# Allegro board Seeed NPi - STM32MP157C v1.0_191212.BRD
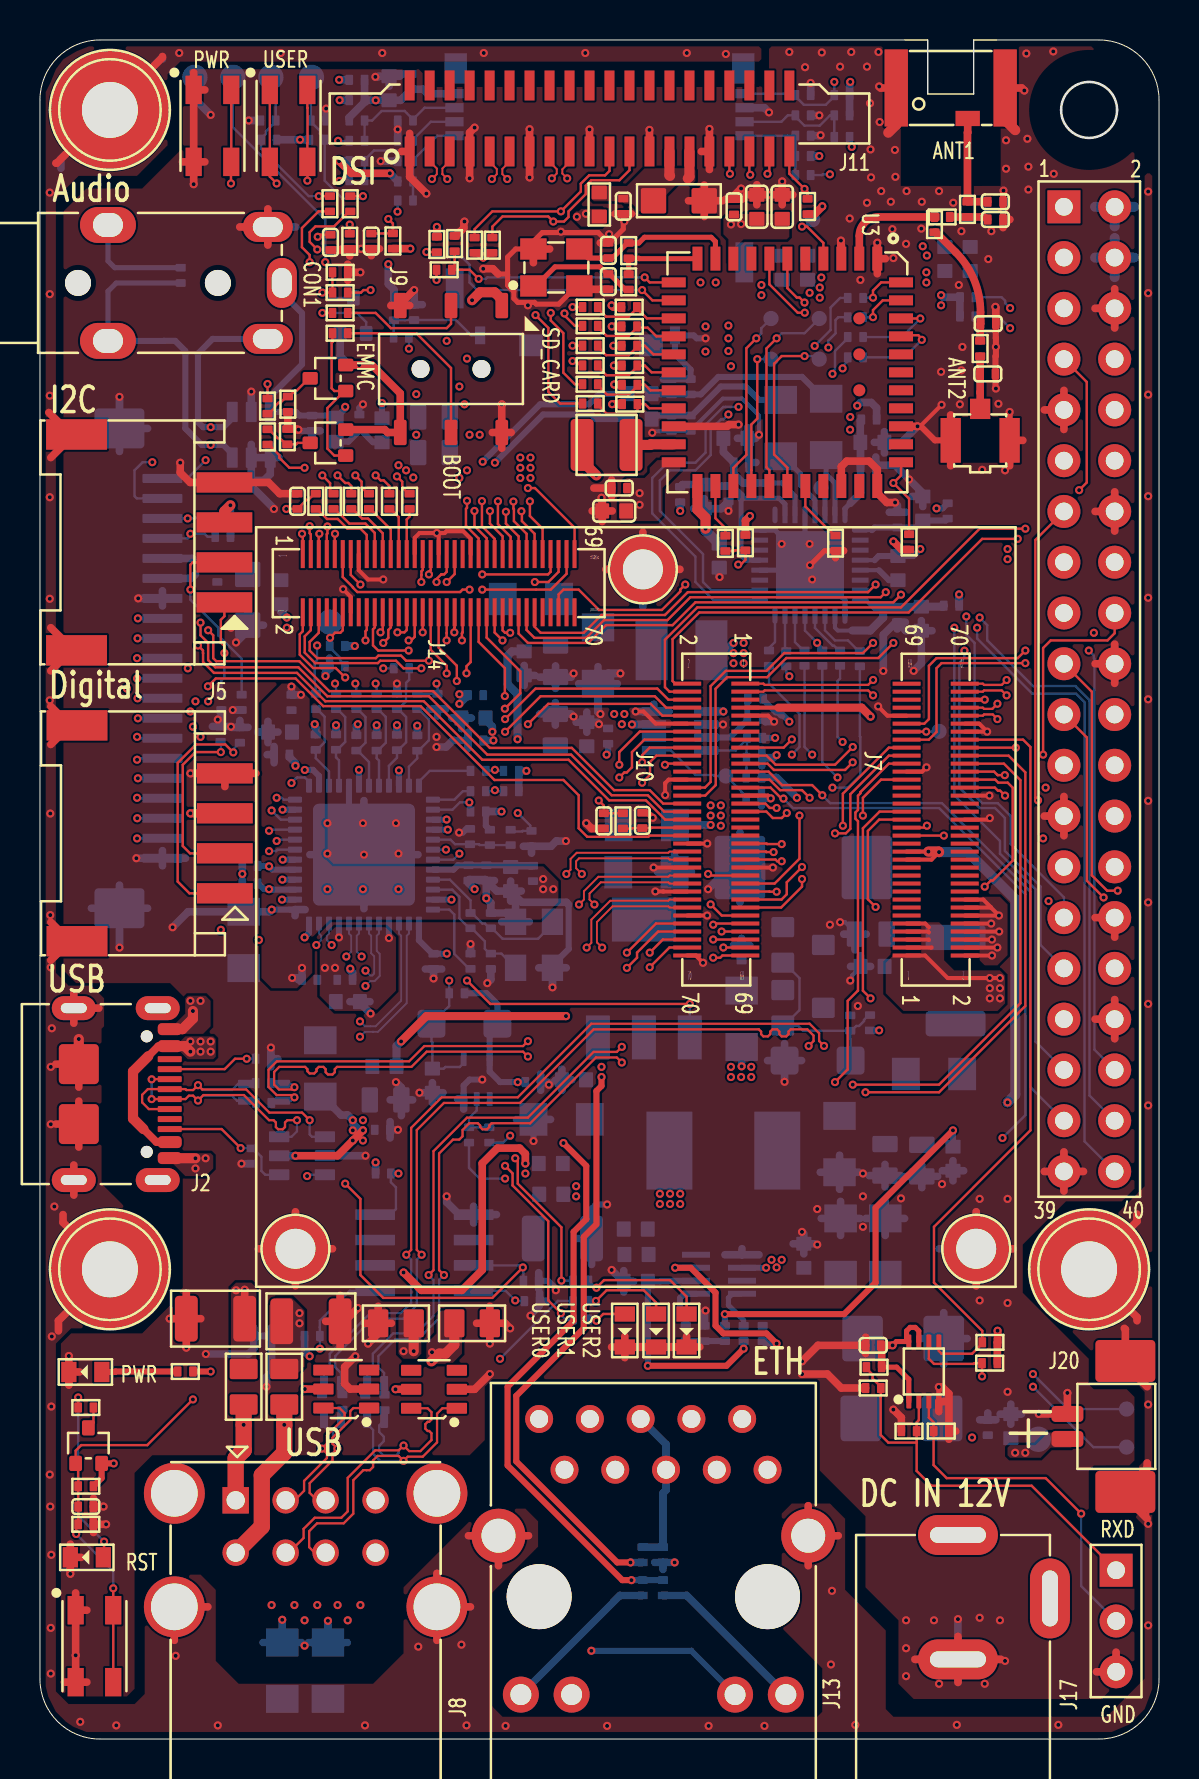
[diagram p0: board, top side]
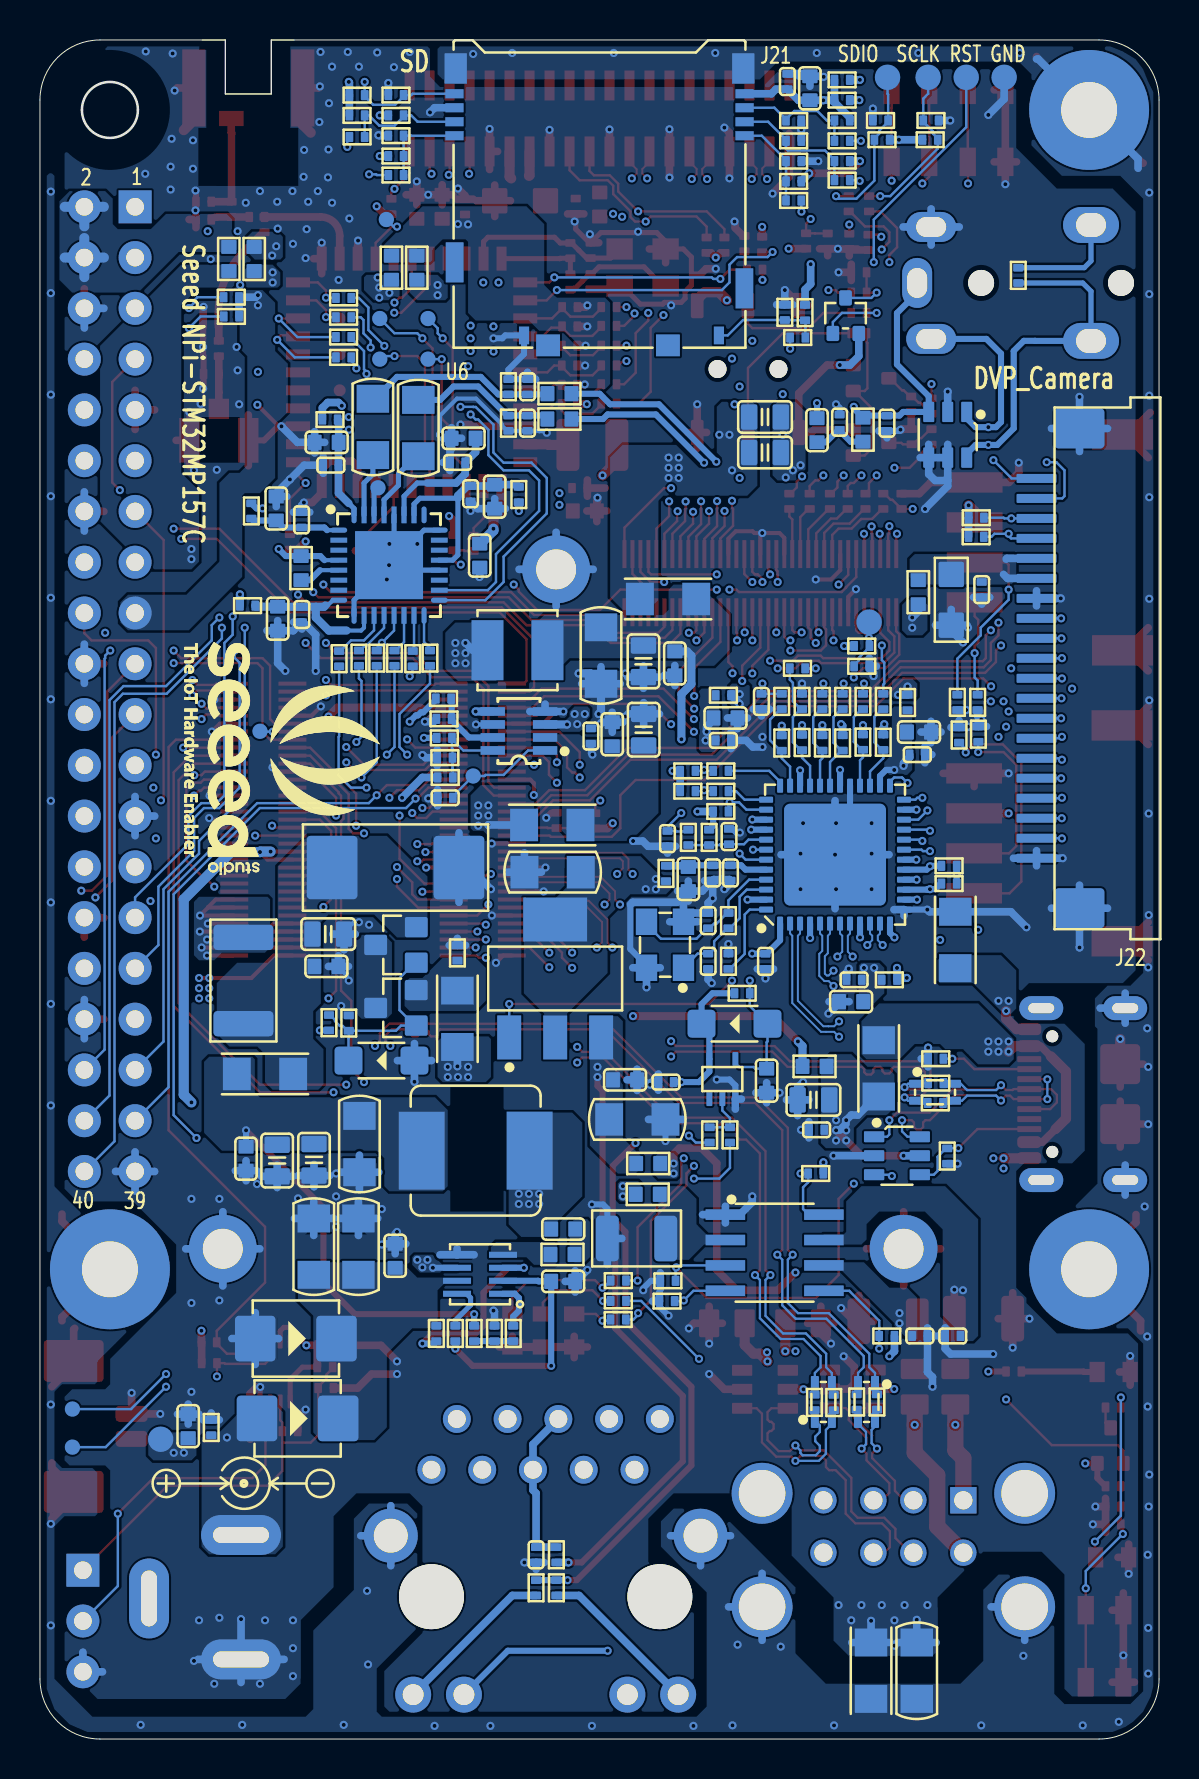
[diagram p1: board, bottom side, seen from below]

Outline 56 x 85 mm; copper layers: TOP, LYR2_GND, LYR3, LYR4, LYR5_PWR, BOTTOM. Coordinates in mm from the lower left corner of the outline.
Outline path: 0,82 0,3 arc(0.88,0.88) 3,0 53,0 arc(55.12,0.88) 56,3 56,82 arc(55.12,84.12) 53,85 46.73,85 46.73,82.3 44.42,82.3 44.42,85 3,85 arc(0.88,84.12) 0,82 ; 51.1,81.5 arc(52.5,82.9) 53.9,81.5 arc(52.5,80.1) 51.1,81.5

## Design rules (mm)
constraint set DEFAULT: min track width 0.121
net group DIFFPAIR2: nets GBE1_TRN0 GBE1_TRP0
net group DIFFPAIR3: nets GBE1_TRN1 GBE1_TRP1
net group DIFFPAIR4: nets GBE1_TRN2 GBE1_TRP2
net group DIFFPAIR5: nets GBE1_TRN3 GBE1_TRP3
net group DIFFPAIR36: nets HOST_USB1_DM HOST_USB1_DP
net group DSI_CK: nets DSI_CK_N DSI_CK_P
net group DSI_D0: nets DSI_D0_N DSI_D0_P
net group DSI_D1: nets DSI_D1_N DSI_D1_P
net group HOST_USB2: nets HOST_USB2_DM HOST_USB2_DP
net group OTG_FS: nets OTG_FS_DM OTG_FS_DP
net group OTG_USB: nets OTG_USB_DM OTG_USB_DP
net group USB1: nets USB1_N USB1_P
net group USB2: nets USB2_N USB2_P
net group DVP: nets DVP_D0 DVP_D1 DVP_D2 DVP_D3 DVP_D4 DVP_D5 DVP_D6 DVP_D7 DVP_HSYNC DVP_PCLK DVP_VSYNC MOC1
net group ETH_RX: nets ETH_RX_CLK ETH_RX_DV ETH_RXD0 ETH_RXD1 ETH_RXD2 ETH_RXD3
net group ETH_TX: nets ETH_GTX_CLK ETH_TX_EN ETH_TXD0 ETH_TXD1 ETH_TXD2 ETH_TXD3
net group MG1_RGMII1_TX: nets RGMII1_TD0
net group RGMII_RX: nets RGMII1_RCLK RGMII1_RCTL RGMII1_RD0 RGMII1_RD1 RGMII1_RD2 RGMII1_RD3
net group RGMII_TX: nets RGMII1_TCLK RGMII1_TCTL RGMII1_TD1 RGMII1_TD2 RGMII1_TD3
net group SD: nets SD_CLK SD_CMD SD_DAT0 SD_DAT1 SD_DAT2 SD_DAT3
net group SDMMC1: nets SDMMC1_CK SDMMC1_CMD SDMMC1_D0 SDMMC1_D1 SDMMC1_D2 SDMMC1_D3
net group SDMMC3: nets SDMMC3_CLK SDMMC3_CMD SDMMC3_D0 SDMMC3_D1 SDMMC3_D2 SDMMC3_D3
nets with their own width: min track width 0.381; nets GND

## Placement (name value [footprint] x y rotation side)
ANT1  ACA-5036-A2-CC-S  [ACA5036]  45.57 82.6 270 top
C1  10pF  [C0402]  2.29 11.63 0 top
C2  47uF  [AVX_B]  8.78 21.03 180 top
C3  100nF  [C0402]  10.32 20.16 0 bottom
C4  100pF  [C0402]  31.6 67.65 90 bottom
C5  100pF  [C0402]  31.6 65.83 270 bottom
C6  100nF  [C0402]  11.97 20.16 180 bottom
C7  47uF  [AVX_B]  13.56 20.9 0 top
C8  22pF  [C0402]  28.44 74.47 90 top
C9  22pF  [C0402]  28.44 72.91 270 top
C10  1uF  [C0603]  28.74 61.44 180 top
C11  22pF  [C0402]  30.14 45.96 90 top
C12  100nF  [C0402]  28.99 62.58 180 top
C13  100nF  [C0402]  29.19 76.68 270 top
C14  22pF  [C0402]  28.22 45.93 270 top
C15  10uF  [AVX_A]  31.97 76.96 0 top
C16  100nF  [C0402]  34.73 76.65 90 top
C17  10uF  [C0603]  35.87 76.65 90 top
C18  10uF  [C0603]  37.14 76.65 90 top
C19  1nF  [C0402]  35.72 47.09 0 bottom
C20  10pF  [C0402]  12.89 61.92 90 top
C21  10pF  [C0402]  47.43 68.29 0 top
C22  10pF  [C0402]  47.45 70.81 0 top
C23  10pF  [C0402]  47.81 76.91 0 top
C24  10pF  [C0402]  47.81 76.02 0 top
C25  100nF  [C0603]  48.58 15.65 90 bottom
C26  10uF  [C0805]  25.79 50.49 90 bottom
C27  10uF  [C0603]  27.36 50.27 90 bottom
C28  10pF  [C0402]  19.9 51.91 270 bottom
C29  100nF  [C0402]  28.43 50.18 90 bottom
C30  10uF  [C0603]  21.69 51.08 180 bottom
C31  100uF  [C1206]  30.35 43.37 0 bottom
C32  10uF  [C0603]  12.01 50.38 180 bottom
C33  100nF  [C0402]  12.1 49.25 180 bottom
C34  100nF  [C0402]  21.8 49.96 180 bottom
C35  100nF  [C0402]  41.7 19.7 0 top
C36  100nF  [C0603]  29.81 25.51 180 bottom
C37  4.7uF  [C1206]  42.3 24.63 90 bottom
C38  4.7uF  [C1206]  40.06 24.63 90 bottom
C39  100nF  [C0603]  38.22 24.17 90 bottom
C40  22uF  [C1206]  40.01 29.77 270 bottom
C41  100nF  [C0402]  21.45 43.33 270 bottom
C42  10nF  [C0402]  22.33 43.33 270 bottom
C43  10uF  [C0603]  23.55 43.02 270 bottom
C44  22uF  [C1206]  27.93 54.2 270 bottom
C45  22uF  [C0805]  42.29 28.98 270 bottom
C46  100nF  [C0603]  24.23 53.81 270 bottom
C47  22pF  [C0402]  22.56 40.94 270 bottom
C48  100nF  [C0402]  31.17 9.22 270 bottom
C49  10uF  [C0603]  33.99 59.2 270 bottom
C50  22uF  [C0805]  44.13 28.94 270 bottom
C51  22pF  [C0402]  22.56 38.91 90 bottom
C52  100nF  [C0402]  19.7 38.9 270 bottom
C53  100nF  [C0603]  45.69 29.03 270 bottom
C54  100nF  [C0603]  29.82 22.9 180 bottom
C55  100nF  [C0402]  15.26 37.98 0 bottom
C56  330uF  [AVX_D]  38.21 43.6 180 bottom
C57  10uF  [C0603]  26.72 32.98 180 bottom
C58  10uF  [C0603]  15.41 36.89 0 bottom
C59  100uF  [C1206]  26.11 31 180 bottom
C60  10uF  [C0805]  41.57 40.27 180 bottom
C61  100nF  [C0603]  41.67 38.65 180 bottom
C62  100nF  [C0402]  24.67 32.86 0 bottom
C63  22uF  [C0805]  25.8 53.92 270 bottom
C64  10uF  [C0805]  19.72 66.14 180 bottom
C65  10uF  [C0603]  19.64 32.94 270 bottom
C66  10uF  [C0805]  19.72 64.36 180 bottom
C68  33pF  [C0402]  13.61 65.83 270 bottom
C70  10uF  [C0603]  44.18 61.56 90 bottom
C71  33pF  [C0402]  15.98 65.88 90 bottom
C72  10uF  [C0603]  44.11 56.05 270 bottom
C73  4.7pF  [C0402]  24.6 45.05 270 bottom
C74  10uF  [C0603]  17.12 65.48 90 bottom
C75  100nF  [C0402]  42.91 60.99 90 bottom
C76  100nF  [C0402]  42.9 56.26 270 bottom
C77  47uF  [AVX_B]  26.14 25.04 0 bottom
C78  10uF  [C0603]  41.65 64.87 0 bottom
C79  100nF  [C0402]  41.44 63.73 0 bottom
C80  10pF  [C0402]  21.52 45.15 90 bottom
C81  100uF  [C1206]  39.34 65.64 90 bottom
C82  100nF  [C0402]  18.6 82.92 90 bottom
C83  10uF  [C0603]  17.47 82.58 90 bottom
C84  100uF  [C1206]  37.07 65.58 90 bottom
C90  100nF  [C0402]  35.1 63.86 0 bottom
C91  1nF  [C1206]  12.12 3.42 90 bottom
C92  10uF  [C0603]  34.8 65.07 0 bottom
C93  100nF  [C0402]  34.45 62.3 270 bottom
C94  10pF  [C0402]  16.58 74.94 270 top
C95  10uF  [C0603]  33.24 62.15 270 bottom
C97  10uF  [AVX_A]  10.4 56.99 270 bottom
C98  10uF  [C0805]  17.29 31.98 0 bottom
C99  100nF  [C0402]  17.14 30.48 0 bottom
C100  100nF  [C0402]  8.87 57.5 270 bottom
C102  10pF  [C0402]  14.54 74.88 270 top
CON1  PJ322  [AUDIO_5P_MJ2135_5D6_14_7X7X6MM]  -2.6 72.85 0 top
D1  ESDPSA0402V05  [D0402]  2.29 10.74 0 top
D2  ESDPSA0402V05  [D0402]  10 50.23 90 bottom
D3  ESDPSA0402V05  [D0402]  9.04 50.27 90 bottom
D4  MBRS240LT3  [DO_214AA_SMB]  43.11 16.04 180 bottom
D5  ESDPSA0402V05  [D0402]  38.18 82.24 0 bottom
D6  ESDPSA0402V05  [D0402]  38.18 81.23 0 bottom
D7  ESDPSA0402V05  [D0402]  38.18 80.21 0 bottom
D8  ESDPSA0402V05  [D0402]  45.1 15.4 0 top
D9  ESDPSA0402V05  [D0402]  43.49 15.4 180 top
D10  1N4148W  [SOD_123]  21.24 35.79 0 bottom
D11  SMBJ24CA  [DO_214AA_SMB]  43.19 20.03 180 bottom
D12  ESDPSA0402V05  [D0402]  18.73 71.37 90 bottom
D13  ESDPSA0402V05  [D0402]  18.28 80.97 180 bottom
D14  ESDPSA0402V05  [D0402]  18.28 79.95 180 bottom
D15  ESDPSA0402V05  [D0402]  18.28 78.94 180 bottom
D16  1N4148W  [SOD_123]  38.91 33.94 0 bottom
D17  ESDPSA0402V05  [D0402]  9.08 51.86 270 bottom
D18  ESDPSA0402V05  [D0402]  10.09 51.86 270 bottom
D20  ESDPSA0402V05  [D0402]  13.94 80.97 0 bottom
D21  ESDPSA0402V05  [D0402]  11.41 80.97 180 bottom
F1  3A  [F1812]  45.82 37.95 90 bottom
FB1  100R  [L0603]  30 67.31 180 bottom
FB2  100R  [L0603]  30.01 66.04 180 bottom
FB3  30R  [L0603]  27.99 76.77 90 top
FB4  120R  [L0603]  46.55 74.04 90 bottom
FB5  120R  [L0603]  45.28 74.04 90 bottom
FB6  120R  [L0402]  12.58 51.85 270 bottom
FB7  120R  [L0603]  38.41 73.61 90 bottom
FB8  120R  [L0603]  37.14 73.61 90 bottom
FB9  120R  [L0402]  24.67 43.3 90 bottom
FB10  120R  [L0603]  25.56 28.79 0 bottom
FB11  2500R  [L0603]  14.82 65.5 270 bottom
FB12  120R  [L0402]  15.86 83.01 0 bottom
FB13  120R  [L0402]  15.86 81.99 0 bottom
FB14  30R  [L0603]  12.05 57.38 90 bottom
J1  4P-2.0mm-90D  [JST4P_SMD_2_0_90D]  9.23 59.86 90 top
J2  USB2.0 Type C  [USB2_0_TYPE_C]  6.44 32.26 0 top
J3  Header 1P  [PTH_2_75MM_5D9]  3.5 81.5 0 top
J4  Header 1P  [PTH_2_75MM_5D9]  3.5 23.5 0 top
J5  4P-2.0mm-90D  [JST4P_SMD_2_0_90D]  9.25 45.31 90 top
J6  Header 1P  [PTH_2MM_3D4]  46.85 24.53 180 top
J7  DF40C(2.0)-70DS-0.4V(51)  [BTB2X35_0D4_16_6X3X2MM]  44.82 46 180 top
J8  USB-AF-90  [ST-USB-201C]  13.29 6.61 180 top
J9  Toggle Switch_2CH  [SW6_2D54_SMD_7_0X3_5X1_5MM]  20.57 68.54 270 top
J10  DF40C(2.0)-70DS-0.4V(51)  [BTB2X35_0D4_16_6X3X2MM]  33.84 46 0 top
J11  YL002-007-020  [HEADER_2X20_1MM]  28 81.07 180 top
J12  Header 1P  [PTH_2MM_3D4]  30.17 58.52 180 top
J13  48F-01GY2DPL2NL  [RJ45_18P_48F-01GY2DPLXNL]  30.69 7.12 0 top
J14  DF40C(2.0)-70DS-0.4V(51)  [BTB2X35_0D4_16_6X3X2MM]  19.95 57.82 90 top
J15  Header 1P  [PTH_2MM_3D4]  12.78 24.53 180 top
J16  U.FL-R-SMT-1(10)  [U-FL3P-SMD-2_6X2_6X1_0MM]  47.05 64.97 90 top
J17  DC-005  [DC_JACK_DC_005_14_2X11X9MM]  45.59 7.03 90 top
J18  Header 1P  [PTH_2_75MM_5D9]  52.5 23.5 0 top
J19  Header 2x20 2.54mm  [HEADER2X20P_2D54_DIP]  52.51 52.52 0 top
J20  Header 1x2 1.25mm  [JST2P_1D25_7_55X3_9X4_8MM]  51.41 15.64 90 top
J21  SCHA5B0200  [SD-MICRO-SCHA5B0300]  28 80.21 0 bottom
J22  YL002-009-020  [JST20P_1D0_27_1X5_3X2_5MM]  6.13 53.57 90 bottom
J24  Header 1x3 2.54mm  [HEADER3P_2D54_DIP]  53.85 5.9 0 top
L1  3.3uH  [L3X3MM]  28.35 64.74 180 top
L2  1uH  [L4X4MM]  32.1 54.47 180 bottom
L3  10uH  [L6_5X6_5]  34.2 29.44 0 bottom
L4  90R  [L2012]  14.64 16.86 270 bottom
L5  90R  [L2012]  16.8 16.86 90 bottom
L6  90R  [L2012]  11.21 32.36 180 bottom
LED1  Blue  [LED0603]  2.34 9.09 180 top
LED2  Red  [LED0603]  30.83 20.44 270 top
LED3  Red  [LED0603]  32.36 20.44 270 top
LED4  Green  [LED0603]  2.27 18.36 180 top
LED5  Red  [LED0603]  29.27 20.44 270 top
NOREF  -  []  9.94 66.01 270 bottom
Q1  CJ2101  [SOT323]  2.42 14.68 0 top
Q2  CJ2101  [SOT323]  14.41 68.07 90 top
Q3  CJ2101  [SOT323]  14.41 64.84 90 top
Q6  FDT434P  [SOT223_4]  30.22 38.05 90 bottom
Q7  IRLML6402TRPBF  [SOT23]  38.19 36.58 90 bottom
Q8  IRLML6402TRPBF  [SOT23]  38.19 39.73 90 bottom
Q9  CJ2101  [SOT323]  15.69 71.21 180 bottom
R1  2K  [R0402]  2.29 16.58 180 top
R2  10K  [R0402]  2.29 12.65 180 top
R3  1K  [R0402]  11.39 65.14 270 top
R4  10K  [R0402]  32.56 67.65 90 bottom
R5  10K  [R0402]  12.38 65.15 90 top
R6  10K  [R0402]  32.56 65.83 270 bottom
R7  10K  [R0402]  12.4 66.78 270 top
R8  1K  [R0402]  11.39 66.68 90 top
R9  4.7K  [R0402]  13.62 20.16 180 bottom
R10  4.7K  [R0402]  17.18 28.29 180 bottom
R11  10K  [R0402]  15.02 73.38 180 top
R12  1K  [R0402]  15.02 72.36 0 top
R13  2K  [R0402]  27.06 21.92 0 bottom
R14  2K  [R0402]  27.06 22.93 0 bottom
R15  1K  [R0402]  15.02 71.35 0 top
R16  1K  [R0402]  15.02 70.33 180 top
R17  4.7K  [R0402]  24.62 21.91 180 bottom
R18  4.7K  [R0402]  21.75 74.73 90 top
R19  10K  [R0402]  19.86 74.77 270 top
R20  4.7K  [R0402]  24.58 22.92 180 bottom
R21  4.7K  [R0402]  22.64 74.73 90 top
R22  10K  [R0402]  20.75 74.81 270 top
R23  33R  [R0402]  27.53 71.64 0 top
R24  33R  [R0402]  27.53 70.7 0 top
R25  33R  [R0402]  27.53 69.71 0 top
R26  33R  [R0402]  27.53 68.72 0 top
R27  33R  [R0402]  27.53 67.78 0 top
R28  33R  [R0402]  27.53 66.81 0 top
R29  1M  [R0402]  29.46 74.46 90 top
R30  0R  [R0402]  29.46 72.9 270 top
R31  10K  [R0402]  29.49 71.63 180 top
R32  10K  [R0402]  29.49 70.67 180 top
R33  10K  [R0402]  29.5 69.7 180 top
R34  10K  [R0402]  29.5 68.71 180 top
R35  10K  [R0402]  29.51 67.75 180 top
R36  10K  [R0402]  29.52 66.78 180 top
R37  49.9R  [R0402]  29.17 45.93 90 top
R38  22R  [R0402]  34.3 59.82 270 top
R39  10K  [R0402]  35.3 59.85 270 top
R40  10K  [R0402]  38.41 76.67 270 top
R41  49.9R  [R0402]  18.5 61.92 90 top
R42  0R  [R0402]  39.81 59.83 270 top
R43  49.9R  [R0402]  17.48 61.92 90 top
R44  49.9R  [R0402]  16.47 61.92 90 top
R45  49.9R  [R0402]  15.58 61.92 90 top
R46  49.9R  [R0402]  14.69 61.92 90 top
R47  10K  [R0402]  43.49 59.89 270 top
R48  100R  [R0402]  13.8 61.92 90 top
R49  0R  [R0402]  45.14 76.15 180 top
R50  0R  [R0402]  46.41 76.53 270 top
R51  0R  [R0402]  44.76 75.76 90 top
R52  0R  [R0402]  47.05 69.56 90 top
R53  49.9R  [R0402]  18.09 53.57 0 bottom
R54  4.7K  [R0402]  46.43 72.13 0 bottom
R55  4.7K  [R0402]  46.42 71.17 0 bottom
R56  49.9R  [R0402]  13.8 51.91 270 bottom
R57  49.9R  [R0402]  14.82 51.91 270 bottom
R58  49.9R  [R0402]  15.83 51.91 270 bottom
R59  49.9R  [R0402]  16.85 51.91 270 bottom
R60  1K  [R0402]  17.86 51.91 90 bottom
R61  100R  [R0402]  18.88 51.91 270 bottom
R62  0R  [R0402]  21.8 52.22 0 bottom
R63  0R  [R1206]  30.36 45.73 180 bottom
R64  10K  [R0402]  14.82 49.87 90 bottom
R65  10K  [R0402]  13.8 49.87 90 bottom
R66  1K  [R0402]  17.86 49.85 90 bottom
R67  100K  [R0402]  35.77 50.09 0 bottom
R68  10K  [R0402]  15.83 49.83 90 bottom
R69  10K  [R0402]  16.85 49.83 90 bottom
R70  10K  [R0402]  18.88 49.83 90 bottom
R71  40.2K  [R0402]  35.78 51.04 0 bottom
R72  0R  [R0402]  14.12 16.86 270 bottom
R73  0R  [R0402]  21.93 48.43 180 bottom
R74  10K  [R0402]  23.58 48.43 180 bottom
R75  180K  [R0402]  35.81 52.05 180 bottom
R76  33R  [R0402]  40.81 72.09 0 bottom
R77  33R  [R0402]  40.81 71.13 0 bottom
R78  33R  [R0402]  40.81 70.14 0 bottom
R79  33R  [R0402]  40.81 69.12 0 bottom
R80  0R  [R0402]  15.13 16.86 270 bottom
R81  10K  [R0402]  40.13 82.24 180 bottom
R82  10K  [R0402]  40.13 81.23 180 bottom
R83  33R  [R0402]  40.13 80.15 180 bottom
R84  0R  [R0402]  21.93 47.42 180 bottom
R85  1.5K  [R0402]  23.58 47.42 180 bottom
R86  0R  [R0402]  17.24 16.84 90 bottom
R87  0R  [R0402]  16.28 16.83 90 bottom
R88  0R  [R0805]  10.19 17.62 270 top
R89  4.7K  [R0402]  21.93 46.4 180 bottom
R90  0R  [R0805]  12.23 17.62 90 top
R91  10K  [R0402]  41.74 18.6 0 top
R92  10K  [R0402]  38.18 79.19 180 bottom
R93  33R  [R0402]  38.18 78.24 180 bottom
R94  10K  [R0402]  22.51 45.11 90 bottom
R95  49.9R  [R0402]  23.55 45.11 270 bottom
R96  100K  [R0402]  41.7 17.56 180 top
R97  4.7K  [R0402]  47.53 18.8 180 top
R98  4.7K  [R0402]  47.54 19.85 180 top
R99  0R  [R1206]  24.57 57.03 0 bottom
R100  1M  [R0402]  21.55 40.94 270 bottom
R101  33R  [R0402]  15.53 76.81 270 top
R102  1K  [R0402]  31.17 7.57 270 bottom
R103  0R  [R0402]  30.16 9.22 90 bottom
R104  1K  [R0402]  30.16 7.57 270 bottom
R105  12.1K  [R0402]  21.55 38.91 90 bottom
R106  10K  [R0402]  10.51 43.68 180 bottom
R107  10K  [R0402]  10.51 42.8 180 bottom
R108  10K  [R0402]  20.86 37.31 180 bottom
R109  0R  [R0402]  13.5 37.98 0 bottom
R110  0R  [R0805]  17.81 20.8 180 top
R111  33R  [R0402]  14.51 76.81 270 top
R112  4.7K  [R0402]  13.86 80.01 0 bottom
R113  4.7K  [R0402]  11.45 80.01 180 bottom
R114  0R  [R0805]  21.62 20.8 0 top
R115  20R  [R0603]  29.85 24.24 180 bottom
R116  2.2k  [R0402]  45.42 61.44 90 bottom
R117  0R  [R0402]  45.61 56.7 180 bottom
R118  0R  [R0402]  11.17 32.81 180 bottom
R119  0R  [R0603]  25.59 27.25 180 bottom
R120  0R  [R0402]  11.19 31.82 180 bottom
R121  5.1K  [R0402]  10.6 29.17 270 bottom
R122  5.1K  [R0402]  11.17 34.03 0 bottom
R123  4.7K  [R0402]  14.88 54.68 180 bottom
R124  4.7K  [R0402]  14.88 53.67 180 bottom
R125  0R  [R0603]  17.24 33.65 180 bottom
R126  0R  [R0603]  42.93 58.58 270 bottom
R127  1M  [R0402]  36.16 20.29 270 bottom
R128  0R  [R0402]  21.47 30.22 90 bottom
R129  0R  [R0402]  22.49 30.22 90 bottom
R130  0R  [R1206]  14.03 33.55 270 bottom
R131  0R  [R0402]  41.49 66.01 180 bottom
R132  0R  [R1206]  10.19 39.98 270 bottom
R133  0R  [R0402]  20.23 73.5 0 top
R134  2K  [R0402]  27.07 20.99 0 bottom
R135  10K  [R0402]  47.43 15.58 90 bottom
R136  0R  [R1206]  44.74 33.27 180 bottom
R137  10R  [R0402]  41.03 54.05 90 bottom
R138  100K  [R0402]  35.21 20.29 90 bottom
R139  41.2K  [R0402]  34.27 20.29 270 bottom
R140  10R  [R0402]  40.04 54.07 90 bottom
R141  10K  [R0402]  18.28 77.92 0 bottom
R142  33R  [R0402]  18.28 76.97 0 bottom
R143  33R  [R0402]  18.08 70.11 180 bottom
R144  51K  [R0402]  32.32 20.29 270 bottom
R145  10R  [R0402]  39.15 54.07 90 bottom
R146  10K  [R0402]  17.71 71.36 270 bottom
R147  7.68K  [R0402]  33.26 20.29 90 bottom
R148  10R  [R0402]  38.26 54.07 90 bottom
R149  0R  [R1206]  14.41 3.42 90 bottom
R150  0R  [R1206]  35.11 36.03 90 bottom
R151  100K  [R0402]  35.11 39.33 90 bottom
R152  4.7K  [R0402]  37.35 54.05 90 bottom
R153  10K  [R0402]  15.86 80.97 0 bottom
R154  33R  [R0402]  15.86 79.95 0 bottom
R155  10K  [R0402]  15.86 78.94 0 bottom
R156  33R  [R0402]  15.86 77.99 0 bottom
R157  10R  [R0402]  36.48 54.07 90 bottom
R158  78.7k  [R0402]  41.54 35.84 90 bottom
R159  100K  [R0402]  40.55 35.82 90 bottom
R160  10K  [R0402]  35.72 48.1 180 bottom
R161  100K  [R0402]  35.74 49.09 0 bottom
R162  2K  [R0402]  7.27 18.39 180 top
R164  10K  [R0402]  17.66 74.94 90 top
R165  0R  [R0402]  32.04 62.26 90 bottom
R167  100R  [R0402]  15.5 74.93 270 top
R172  4.7K  [R0402]  9.15 60.14 180 bottom
R173  4.7K  [R0402]  9.15 61.1 180 bottom
R176  0R  [R0402]  7.04 73.22 90 bottom
SW1  Tactile Switch  [SW_4P]  2.73 4.64 270 top
SW2  Tactile Switch  [SW_4P]  8.63 80.7 270 top
SW3  Tactile Switch  [SW_4P]  12.44 80.7 270 top
TP1  JTRST  [TP30C_SMD]  54.38 16.51 270 bottom
TP2  JTDI  [TP30C_SMD]  54.38 14.6 270 bottom
TP3  TP  [TP60C_SMD]  49.96 15 180 bottom
TP4  A_B_SIDE  [TP30C_SMD]  34.32 48.18 0 bottom
TP5  PCM_IN  [TP30C_SMD]  39 71.06 0 bottom
TP6  PCM_SYNC  [TP30C_SMD]  39 69.03 0 bottom
TP7  FM_RX  [TP30C_SMD]  38.67 76.02 180 bottom
TP8  PCM_OUT  [TP30C_SMD]  36.58 71.06 0 bottom
TP9  PCM_CLK  [TP30C_SMD]  36.58 69.03 0 bottom
TP10  TP  [TP60C_SMD]  13.59 83.13 180 bottom
TP11  TP  [TP60C_SMD]  11.55 83.13 180 bottom
TP12  TP  [TP60C_SMD]  9.65 83.13 180 bottom
TP13  TP  [TP60C_SMD]  7.75 83.13 180 bottom
TP14  TP  [TP60C_SMD]  14.51 55.88 0 bottom
TP15  JTDO_TRACESWO  [TP30C_SMD]  44.99 50.41 0 bottom
TP16  OUT3  [TP30C_SMD]  39.09 62.6 270 bottom
U1  NUP4114HMR6T1G  [SOT23_6]  15.33 17.51 90 top
U2  NUP4114HMR6T1G  [SOT23_6]  13.11 29.18 270 bottom
U3  AP6236  [MODULE44-0_9-12X12X1_5MM]  37.4 68.37 270 top
U4  MP2161GJ  [TSOT23_8_0D65_2X1MM]  32.03 50.43 0 bottom
U5  KSZ9031RNXCA  [QFN48_0D5_7X7MM]  16.21 44.24 90 bottom
U6  NC7WZ126K8X  [US8_0D5_2X2_3X0_7MM]  44.23 18.39 0 top
U7  NUP4114HMR6T1G  [SOT23_6]  19.72 17.5 90 top
U8  74LVC1G07GW  [SOT353]  21.85 33.02 180 bottom
U9  MP9943GQ  [QFN8-0_65-3X3X1MM]  33.98 23.25 0 bottom
U11  WM8960GEFL  [QFN32_0D5_5X5MM_EP3P3MM]  38.53 58.73 270 bottom
U12  STMPS2252MTR  [SO_8_1D27_4_8X3_8MM]  19.24 24.33 270 bottom
U14  ESDA6V1BC6  [SOT23_6]  10.57 65.25 0 bottom
X1  26MHz 16pF  [X4-SMD-3_2X2_5X1_0MM]  25.84 73.62 0 top
X3  25MHz 18pF  [X4-SMD-3_2X2_5X1_0MM]  24.72 39.73 90 bottom

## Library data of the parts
ANT1 = Built-in ANT_3P
C1 C3-C6 C8-C14 C16-C55 C57-C66 C68 C70-C76 C78-C84 C90-C95 C98-C100 C102 = CC
C2 C7 C15 C56 C77 C97 = CT
CON1 = Earphone Jack
D1-D3 D5-D9 D11-D15 D17 D18 D20 D21 = DIODE TVS BI-DIR
D4 D10 D16 = D
F1 = Fuse
FB1-FB14 = FB
J1 J5 = Header_4+2P
J2 = USB2.0_Type C_16+6P
J3 J4 J6 J12 J15 J18 = Header 1P
J7 J10 J14 = Header 2x35
J8 = Dual USB A
J9 = Toggle Switch_2CH
J11 = Header 2x20 Of ST
J13 = RJ45_18P_48F-01
J16 = RF ANT 3P
J17 = Power Jack
J19 = Header 2X20 Of RPI
J20 = Header_2+2P
J21 = MicroSD Card_8P: Tolerance: X; User Part Number: X
J22 = Header 20+2P
J24 = Header 1x3
L1-L3 = L
L4-L6 = CL
LED1-LED5 = Single LED
Q1-Q3 Q7-Q9 = PMOS_123
Q6 = PMOS_1S1G2D
R1-R162 R164 R165 R167 R172 R173 R176 = R
SW1-SW3 = Tactile Switch_4P
TP1-TP16 = TESTPT1
U1 U2 U7 = NUP4114
U3 = Module-WIFI_AP6212
U4 = MP2161
U5 = KSZ9031RNX
U6 = NC7WZ126
U8 = SN74LVC1G07DCK
U9 = MP9943
U11 = WM8960
U12 = STMPS2252MTR
U14 = ESDA6V1BC6
X1 X3 = XTAL_4P

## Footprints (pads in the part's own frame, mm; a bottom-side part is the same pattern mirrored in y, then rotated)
ACA5036
  rect 0.762x1.219 smd: 1(1.525,0.85)
  rect 3.861x1.168 smd: 2(0,2.725) 3(0,-2.725)
AUDIO_5P_MJ2135_5D6_14_7X7X6MM
  round 1.3 hole 1.3 unplated: (4.5,0) (11.5,0)
  oval 1.5x2.5 hole 1x1.5: 1(14.7,0)
  oval 2.5x1.5 hole 1.5x1: 2(14,2.8) 3(14,-2.8)
  oval 2.8x1.8 hole 1.5x1.2: 4(6,2.9) 5(6,-2.9)
AVX_A
  rrect 1.27x1.27 smd: 1(-1.27,0) 2(1.27,0)
AVX_B
  rrect 1.143x2.286 smd: 1(-1.46,0) 2(1.46,0)
AVX_D
  rrect 2.54x3.175 smd: 1(-3.175,0) 2(3.175,0)
BTB2X35_0D4_16_6X3X2MM
  rect 1.4x0.2 smd: 1(1.455,6.8) 2(-1.455,6.8) 3(1.455,6.4) 4(-1.455,6.4) 5(1.455,6) 6(-1.455,6) 7(1.455,5.6) 8(-1.455,5.6) 9(1.455,5.2) 10(-1.455,5.2) 11(1.455,4.8) 12(-1.455,4.8) 13(1.455,4.4) 14(-1.455,4.4) 15(1.455,4) 16(-1.455,4) 17(1.455,3.6) 18(-1.455,3.6) 19(1.455,3.2) 20(-1.455,3.2) 21(1.455,2.8) 22(-1.455,2.8) 23(1.455,2.4) 24(-1.455,2.4) 25(1.455,2) 26(-1.455,2) 27(1.455,1.6) 28(-1.455,1.6) 29(1.455,1.2) 30(-1.455,1.2) 31(1.455,0.8) 32(-1.455,0.8) 33(1.455,0.4) 34(-1.455,0.4) 35(1.455,0) 36(-1.455,0) 37(1.455,-0.4) 38(-1.455,-0.4) 39(1.455,-0.8) 40(-1.455,-0.8) 41(1.455,-1.2) 42(-1.455,-1.2) 43(1.455,-1.6) 44(-1.455,-1.6) 45(1.455,-2) 46(-1.455,-2) 47(1.455,-2.4) 48(-1.455,-2.4) 49(1.455,-2.8) 50(-1.455,-2.8) 51(1.455,-3.2) 52(-1.455,-3.2) 53(1.455,-3.6) 54(-1.455,-3.6) 55(1.455,-4) 56(-1.455,-4) 57(1.455,-4.4) 58(-1.455,-4.4) 59(1.455,-4.8) 60(-1.455,-4.8) 61(1.455,-5.2) 62(-1.455,-5.2) 63(1.455,-5.6) 64(-1.455,-5.6) 65(1.455,-6) 66(-1.455,-6) 67(1.455,-6.4) 68(-1.455,-6.4) 69(1.455,-6.8) 70(-1.455,-6.8)
C0402
  rrect 0.385x0.508 smd: 1(-0.383,0) 2(0.383,0)
C0603
  rrect 0.696x0.762 smd: 1(-0.602,0) 2(0.602,0)
C0805
  rrect 0.819x1.27 smd: 1(-0.79,0) 2(0.79,0)
C1206
  rect 1.397x1.626 smd: 1(-1.41,0) 2(1.41,0)
D0402
  rrect 0.385x0.508 smd: 1(-0.383,0) 2(0.383,0)
DC_JACK_DC_005_14_2X11X9MM
  oval 2x4 hole 0.8x2.8: 1(3.175,-0.35) 2(-3.048,-0.35)
  oval 4x2 hole 2.8x0.8: 3(0,-4.953)
DO_214AA_SMB
  rrect 2.032x2.286 smd: 1(-2.032,0) 2(2.032,0)
F1812
  rrect 1.27x3 smd: 1(-2.159,0) 2(2.159,0)
HEADER2X20P_2D54_DIP
  rect 1.651x1.651 hole 0.889: 1(-1.27,24.13)
  round 1.651 hole 0.889: 2(1.27,24.13) 3(-1.27,21.59) 4(1.27,21.59) 5(-1.27,19.05) 6(1.27,19.05) 7(-1.27,16.51) 8(1.27,16.51) 9(-1.27,13.97) 10(1.27,13.97) 11(-1.27,11.43) 12(1.27,11.43) 13(-1.27,8.89) 14(1.27,8.89) 15(-1.27,6.35) 16(1.27,6.35) 17(-1.27,3.81) 18(1.27,3.81) 19(-1.27,1.27) 20(1.27,1.27) 21(-1.27,-1.27) 22(1.27,-1.27) 23(-1.27,-3.81) 24(1.27,-3.81) 25(-1.27,-6.35) 26(1.27,-6.35) 27(-1.27,-8.89) 28(1.27,-8.89) 29(-1.27,-11.43) 30(1.27,-11.43) 31(-1.27,-13.97) 32(1.27,-13.97) 33(-1.27,-16.51) 34(1.27,-16.51) 35(-1.27,-19.05) 36(1.27,-19.05) 37(-1.27,-21.59) 38(1.27,-21.59) 39(-1.27,-24.13) 40(1.27,-24.13)
HEADER3P_2D54_DIP
  rect 1.651x1.651 hole 0.889: 1(0,2.54)
  round 1.651 hole 0.889: 2(0,0) 3(0,-2.54)
HEADER_2X20_1MM
  rect 0.5x1.5 smd: 1(9.5,1.65) 2(8.5,1.65) 3(7.5,1.65) 4(6.5,1.65) 5(5.5,1.65) 6(4.5,1.65) 7(3.5,1.65) 8(2.5,1.65) 9(1.5,1.65) 10(0.5,1.65) 11(-0.5,1.65) 12(-1.5,1.65) 13(-2.5,1.65) 14(-3.5,1.65) 15(-4.5,1.65) 16(-5.5,1.65) 17(-6.5,1.65) 18(-7.5,1.65) 19(-8.5,1.65) 20(-9.5,1.65) 21(9.5,-1.65) 22(8.5,-1.65) 23(7.5,-1.65) 24(6.5,-1.65) 25(5.5,-1.65) 26(4.5,-1.65) 27(3.5,-1.65) 28(2.5,-1.65) 29(1.5,-1.65) 30(0.5,-1.65) 31(-0.5,-1.65) 32(-1.5,-1.65) 33(-2.5,-1.65) 34(-3.5,-1.65) 35(-4.5,-1.65) 36(-5.5,-1.65) 37(-6.5,-1.65) 38(-7.5,-1.65) 39(-8.5,-1.65) 40(-9.5,-1.65)
JST2P_1D25_7_55X3_9X4_8MM
  rrect 0.8x1.6 smd: 1(-0.625,0) 2(0.625,0)
  rrect 2.1x3 smd: 3(-3.275,-2.9) 4(3.275,-2.9)
JST4P_SMD_2_0_90D
  rect 1.016x2.794 smd: 1(-3,0) 2(-1,0) 3(1,0) 4(3,0)
  rect 1.524x3.048 smd: 5(5.4,7.4) 6(-5.4,7.4)
JST20P_1D0_27_1X5_3X2_5MM
  rrect 0.45x2 smd: 1(-9.5,0) 2(-8.5,0) 3(-7.5,0) 4(-6.5,0) 5(-5.5,0) 6(-4.5,0) 7(-3.5,0) 8(-2.5,0) 9(-1.5,0) 10(-0.5,0) 11(0.5,0) 12(1.5,0) 13(2.5,0) 14(3.5,0) 15(4.5,0) 16(5.5,0) 17(6.5,0) 18(7.5,0) 19(8.5,0) 20(9.5,0)
  rrect 2x2.5 smd: 21(-12,-2.15) 22(12,-2.15)
L3X3MM
  rrect 1.15x2.6 smd: 1(-1.225,0) 2(1.225,0)
L4X4MM
  rect 1.6x3 smd: 1(-1.5,0) 2(1.5,0)
L6_5X6_5
  rect 2.3x3.9 smd: 1(-2.7,0) 2(2.7,0)
L0402
  rrect 0.385x0.508 smd: 1(-0.383,0) 2(0.383,0)
L0603
  rrect 0.696x0.762 smd: 1(-0.602,0) 2(0.602,0)
L2012
  rrect 0.75x0.4 smd: 1(-0.925,0.425) 2(0.925,0.425) 3(0.925,-0.425) 4(-0.925,-0.425)
LED0603
  rect 0.762x1.016 smd: 1(-0.826,0) 2(0.826,0)
MODULE44-0_9-12X12X1_5MM
  rect 1.2x0.5 smd: 1(-5.688,4.5) 2(-5.688,3.6) 3(-5.688,2.7) 4(-5.688,1.8) 5(-5.688,0.9) 6(-5.688,0) 7(-5.688,-0.9) 8(-5.688,-1.8) 9(-5.688,-2.7) 10(-5.688,-3.6) 11(-5.688,-4.5) 23(5.688,-4.5) 24(5.688,-3.6) 25(5.688,-2.7) 26(5.688,-1.8) 27(5.688,-0.9) 28(5.688,0) 29(5.688,0.9) 30(5.688,1.8) 31(5.688,2.7) 32(5.688,3.6) 33(5.688,4.5)
  rect 0.5x1.2 smd: 12(-4.5,-5.688) 13(-3.6,-5.688) 14(-2.7,-5.688) 15(-1.8,-5.688) 16(-0.9,-5.688) 17(0,-5.688) 18(0.9,-5.688) 19(1.8,-5.688) 20(2.7,-5.688) 21(3.6,-5.688) 22(4.5,-5.688) 34(4.5,5.688) 35(3.6,5.688) 36(2.7,5.688) 37(1.8,5.688) 38(0.9,5.688) 39(0,5.688) 40(-0.9,5.688) 41(-1.8,5.688) 42(-2.7,5.688) 43(-3.6,5.688) 44(-4.5,5.688)
  round 0.6 smd: 45(-2.7,3.6) 46(-0.9,3.6) 47(0.9,3.6)
PTH_2_75MM_5D9
  round 6 hole 2.8: 1(0,0)
PTH_2MM_3D4
  round 3.4 hole 2: 1(0,0)
QFN8-0_65-3X3X1MM
  rect 1.4x0.3 smd: 1(-1.15,0.975) 2(-1.15,0.325) 3(-1.15,-0.325) 4(-1.15,-0.975) 5(1.15,-0.975) 6(1.15,-0.325) 7(1.15,0.325) 8(1.15,0.975)
QFN32_0D5_5X5MM_EP3P3MM
  oval 0.254x0.838 smd: 1(-1.751,-2.515) 8(1.751,-2.515) 17(1.751,2.515) 24(-1.751,2.515)
  rect 0.254x0.838 smd: 2(-1.251,-2.515) 3(-0.751,-2.515) 4(-0.25,-2.515) 5(0.25,-2.515) 6(0.751,-2.515) 7(1.251,-2.515) 18(1.251,2.515) 19(0.751,2.515) 20(0.25,2.515) 21(-0.25,2.515) 22(-0.751,2.515) 23(-1.251,2.515)
  oval 0.838x0.254 smd: 9(2.515,-1.751) 16(2.515,1.751) 25(-2.515,1.751) 32(-2.515,-1.751)
  rect 0.838x0.254 smd: 10(2.515,-1.251) 11(2.515,-0.751) 12(2.515,-0.25) 13(2.515,0.25) 14(2.515,0.751) 15(2.515,1.251) 26(-2.515,1.251) 27(-2.515,0.751) 28(-2.515,0.25) 29(-2.515,-0.25) 30(-2.515,-0.751) 31(-2.515,-1.251)
  rect 3.404x3.404 smd: 33(0,0)
QFN48_0D5_7X7MM
  rrect 0.7x0.3 smd: 1(-3.45,2.75) 2(-3.45,2.25) 3(-3.45,1.75) 4(-3.45,1.25) 5(-3.45,0.75) 6(-3.45,0.25) 7(-3.45,-0.25) 8(-3.45,-0.75) 9(-3.45,-1.25) 10(-3.45,-1.75) 11(-3.45,-2.25) 12(-3.45,-2.75) 25(3.45,-2.75) 26(3.45,-2.25) 27(3.45,-1.75) 28(3.45,-1.25) 29(3.45,-0.75) 30(3.45,-0.25) 31(3.45,0.25) 32(3.45,0.75) 33(3.45,1.25) 34(3.45,1.75) 35(3.45,2.25) 36(3.45,2.75)
  rrect 0.3x0.7 smd: 13(-2.75,-3.45) 14(-2.25,-3.45) 15(-1.75,-3.45) 16(-1.25,-3.45) 17(-0.75,-3.45) 18(-0.25,-3.45) 19(0.25,-3.45) 20(0.75,-3.45) 21(1.25,-3.45) 22(1.75,-3.45) 23(2.25,-3.45) 24(2.75,-3.45) 37(2.75,3.45) 38(2.25,3.45) 39(1.75,3.45) 40(1.25,3.45) 41(0.75,3.45) 42(0.25,3.45) 43(-0.25,3.45) 44(-0.75,3.45) 45(-1.25,3.45) 46(-1.75,3.45) 47(-2.25,3.45) 48(-2.75,3.45)
  rrect 5.1x5.1 smd: 49(0,0)
R0402
  rrect 0.385x0.508 smd: 1(-0.383,0) 2(0.383,0)
R0603
  rrect 0.696x0.762 smd: 1(-0.602,0) 2(0.602,0)
R0805
  rrect 1.016x1.397 smd: 1(-0.889,0) 2(0.889,0)
R1206
  rect 1.397x1.626 smd: 1(-1.41,0) 2(1.41,0)
RJ45_18P_48F-01GY2DPLXNL
  round 3.25 hole 3.25 unplated: (-5.715,0) (5.715,0)
  round 1.4 hole 0.9: 1(-5.715,8.89) 2(-4.445,6.35) 3(-3.175,8.89) 4(-1.905,6.35) 5(-0.635,8.89) 6(0.635,6.35) 7(1.905,8.89) 8(3.175,6.35) 9(4.445,8.89) 10(5.715,6.35)
  round 1.8 hole 1.05: 11(-6.63,-4.9) 12(-4.09,-4.9) 13(4.09,-4.9) 14(6.63,-4.9)
  round 2.7 hole 1.7: 15(-7.75,3.05) 16(7.75,3.05)
SD-MICRO-SCHA5B0300
  rect 0.914x0.457 smd: 1(-7.257,0) 2(-7.257,-0.7) 3(-7.257,-1.4) 4(-7.257,-2.1) 5(7.257,-2.1) 6(7.257,-1.4) 7(7.257,-0.7) 8(7.257,0)
  rect 0.508x0.889 smd: 9(3.775,9.989) 10(-5.975,9.989)
  rect 0.889x2.007 smd: 11(-7.25,7.635) 12(7.25,6.335)
  rect 1.118x1.524 smd: 13(-7.196,-3.365) 14(7.196,-3.365)
  rect 1.194x1.092 smd: 15(-3.425,10.488) 16(2.575,10.488)
SO_8_1D27_4_8X3_8MM
  rect 0.53x1.98 smd: 1(-1.905,-2.465) 2(-0.635,-2.465) 3(0.635,-2.465) 4(1.905,-2.465) 5(1.905,2.465) 6(0.635,2.465) 7(-0.635,2.465) 8(-1.905,2.465)
SOD_123
  rrect 1.397x1.397 smd: 1(-1.651,0) 2(1.651,0)
SOT23
  rrect 1.016x1.143 smd: 1(-0.889,-1.016) 2(0.889,-1.016) 3(0,1.016)
SOT23_6
  rrect 0.55x1.016 smd: 1(-0.95,-1.143) 2(0,-1.143) 3(0.95,-1.143) 4(0.95,1.143) 5(0,1.143) 6(-0.95,1.143)
SOT223_4
  rect 2.2x1.2 smd: 1(-2.95,2.3) 2(-2.95,0) 3(-2.95,-2.3)
  rect 2.2x3.2 smd: 4(2.95,0)
SOT323
  rrect 0.635x0.762 smd: 1(-0.635,-0.889) 2(0.665,-0.889) 3(0,0.889)
SOT353
  rrect 0.3x0.7 smd: 1(-0.65,-1) 2(0,-1) 3(0.65,-1) 4(0.65,1) 5(-0.65,1)
ST-USB-201C
  rect 1.321x1.321 hole 0.914: A1(3.5,-5.33)
  round 1.321 hole 0.914: A2(1,-5.33) A3(-1,-5.33) A4(-3.5,-5.33) B1(3.5,-2.71) B2(1,-2.71) B3(-1,-2.71) B4(-3.5,-2.71)
  round 3.048 hole 2.337: S1(6.57,-5.68) S2(-6.57,-5.68) S3(-6.57,0) S4(6.57,0)
SW6_2D54_SMD_7_0X3_5X1_5MM
  round 0.9 hole 0.9 unplated: (0,1.524) (0,-1.524)
  rrect 1.27x0.635 smd: 1(-3.175,2.54) 2(-3.175,0) 3(-3.175,-2.54) 4(3.175,-2.54) 5(3.175,0) 6(3.175,2.54)
SW_4P
  rect 1.422x0.813 smd: 1(-1.8,-0.94) 2(-1.8,0.94) 3(1.8,-0.94) 4(1.8,0.94)
TP30C_SMD
  round 0.762 smd: 1(0,0)
TP60C_SMD
  round 1.27 smd: 1(0,0)
TSOT23_8_0D65_2X1MM
  rect 1.219x0.432 smd: 1(-1.31,0.975) 2(-1.31,0.325) 3(-1.31,-0.325) 4(-1.31,-0.975) 5(1.31,-0.975) 6(1.31,-0.325) 7(1.31,0.325) 8(1.31,0.975)
U-FL3P-SMD-2_6X2_6X1_0MM
  rect 1.016x1.016 smd: 1(1.575,0)
  rect 2.235x1.016 smd: 2(0,1.475) 3(0,-1.475)
US8_0D5_2X2_3X0_7MM
  rrect 0.25x0.7 smd: 1(-0.75,-1.5) 2(-0.25,-1.5) 3(0.25,-1.5) 4(0.75,-1.5) 5(0.75,1.5) 6(0.25,1.5) 7(-0.25,1.5) 8(-0.75,1.5)
USB2_0_TYPE_C
  round 0.6 hole 0.6 unplated: (-1.1,2.89) (-1.1,-2.89)
  rrect 1.2x0.3 smd: A5(0.05,1.25) A6(0.05,0.25) A7(0.05,-0.25) A8(0.05,-1.25) B5(0.05,-1.75) B6(0.05,-0.75) B7(0.05,0.75) B8(0.05,1.75)
  rrect 1.2x0.6 smd: B1(0.05,-3.2) B4(0.05,-2.4) B9(0.05,2.4) B12(0.05,3.25)
  oval 2.2x1.2 hole 1.3x0.5: S1(-4.75,4.3) S2(-0.55,4.3) S3(-4.75,-4.3) S4(-0.55,-4.3)
  rrect 2x2 smd: S5(-4.5,1.5) S6(-4.5,-1.5)
X4-SMD-3_2X2_5X1_0MM
  rect 1.321x1.067 smd: 1(-1.15,-0.925) 2(1.15,-0.925) 3(1.15,0.925) 4(-1.15,0.925)

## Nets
3V3_DC: C64.1 C66.1 FB3.1 FB5.1 FB7.1 FB10.1 FB13.1 FB14.1 J1.3 J5.3 R18.1 R21.1 R40.2 R62.1 R99.2 R117.1 R131.1 R162.1 R172.1 R173.1
3V3_RPI: FB5.2 J19.1 J19.17 R54.1 R55.1
3V3_SD: C82.1 C83.1 FB12.2 FB13.2 J21.4 R81.1 R82.1 R92.1 R141.1 R146.1 R153.1 R155.1
3V3_SYS: C35.2 C64.2 C66.2 FB8.1 FB12.1 J7.1 J7.3 J7.5 J7.7 J7.9 J9.1 J9.4 Q1.2(S) Q2.2(S) Q3.2(S) Q9.2(S) R2.1 R9.2 R10.2 R91.2 R97.1 R98.1 R112.1 R113.1 R123.1 R160.1 R164.1 U6.1 U6.7 U6.8(VCC)
3V3_WIFI: C10.1 C12.1 C16.1 C17.1 C18.1 FB7.2 FB8.2 R19.1 R31.2 R32.2 R33.2 R34.2 R35.2 R36.2 R39.1 R47.2 U3.9 U3.22
5V_DC: C56.1 C60.1 C61.1 F1.1 Q8.2(S) R136.2
5V_IN: F1.2 FB4.1 J7.2 J7.4 J7.6 J7.8 J7.10 J7.12 J7.14 J7.16 R63.1 R119.1 R165.1
5V_RPI: FB4.2 J19.2 J19.4
5V_USB: C98.1 C99.1 R125.2 R130.2 R150.1 U2.5(VCC)
GND: ANT1.2 ANT1.3(GND#3) C1.2 C2.2 C3.2 C4.2 C5.2 C6.2 C7.2 C8.2 C9.2 C10.2 C11.2 C12.2 C13.2 C14.2 C15.2 C16.2 C17.2 C18.2 C19.2 C20.2 C21.2 C22.2 C23.2 C24.2 C25.2 C26.2 C27.2 C28.2 C29.2 C30.2 C31.2 C32.2 C33.2 C34.2 C35.1 C37.2 C38.2 C39.2 C40.2 C41.2 C42.2 C43.2 C44.2 C45.2 C46.2 C47.1 C48.2 C49.2 C50.2 C51.1 C52.2 C53.2 C54.2 C55.2 C56.2 C57.2 C58.2 C59.2 C60.2 C61.2 C62.2 C63.2 C65.2 C68.2 C70.2 C71.2 C72.2 C73.2 C75.2 C76.2 C77.2 C78.2 C79.2 C80.2 C82.2 C83.2 C90.2 C91.2 C92.2 C93.2 C94.2 C95.2 C97.2 C98.2 C99.2 C100.2 C102.2 CON1.2 D1.2 D2.2 D3.2 D5.2 D6.2 D7.2 D8.2 D9.2 D11.1 D12.2 D13.2 D14.2 D15.2 D16.1 D17.2 D18.2 D20.2 D21.2 J1.4 J5.4 J6.1 J7.36 J7.42 J7.47 J7.58 J7.60 J7.61 J7.66 J9.3 J9.6 J10.9 J10.12 J10.26 J10.29 J10.42 J10.47 J10.48 J10.54 J10.60 J10.70 J11.1 J11.4 J11.7 J11.10 J11.13 J11.16 J12.1 J14.14 J14.15 J14.29 J14.35 J14.43 J15.1 J16.2 J16.3(SHIELD2) J17.2 J19.6 J19.9 J19.14 J19.20 J19.25 J19.30 J19.34 J19.39 J20.2 J21.6(VSS) J21.9 J22.1 J22.14 J22.21 J22.22(PAD2) J24.3 LED1.2(C) LED2.2(C) LED3.2(C) LED4.2(C) LED5.2(C) R4.2 R5.2 R6.2 R7.2 R11.1 R17.1 R20.1 R22.1 R42.2 R60.2 R71.2 R96.2 R105.2 R110.2 R114.2 R121.2 R122.2 R124.2 R132.1 R135.2 R147.2 R149.2 R151.2 R159.2 R161.2 R167.2 SW1.1 SW1.3 SW2.1 SW2.3 TP13.1(TP) U1.2 U2.2 U3.1 U3.3 U3.20 U3.31 U3.33 U3.36 U4.4 U4.6 U5.13 U5.29 U5.49 U6.4 U7.2 U8.3 U9.5 U11.9 U11.20 U11.24 U11.28 U11.33 U12.1 U14.2 U14.4 U14.5 X1.2 X1.4 X3.2 X3.4
GND_EARTH: C91.1 J1.5 J1.6 J2.S1 J2.S3 J2.S5 J2.S6 J3.1 J4.1 J5.5 J5.6 J8.S3 J8.S4 J13.15 J13.16 J18.1 J20.3 J20.4 J21.13 J21.14 R149.1
VBAT: C25.1 J7.25 J7.27 J20.1 TP3.1(TP)
26M_XTAL_IN: C8.1 R29.2 U3.10 X1.3
26M_XTAL_OUT: R29.1 R30.1 U3.11(XTAL_OUT)
BOOT0: J10.6 R8.2
BOOT1: J10.8 R12.2
BOOT2: J10.10 R3.2
BOOT_MODE0: Q9.1 R15.1
BOOT_MODE1: Q2.1 Q3.1 R16.2
BT_HOST_WAKE: J14.60 U3.7
BT_RST: J14.56 R47.1 U3.34
BT_UART_CTS: R76.2 U3.44
BT_UART_RTS: R79.2 U3.41
BT_UART_RX: R77.2 U3.43
BT_UART_TX: R78.2 U3.42
BT_WAKE: J14.58 U3.6
DC_12V: C37.1 C38.1 C39.1 D4.2(C) D11.2 R127.1 U9.7
DSI_CK_N: J10.50 J11.5
DSI_CK_P: J10.52 J11.6
DSI_D0_N: J10.56 J11.8
DSI_D0_P: J10.58 J11.9
DSI_D1_N: J10.44 J11.2
DSI_D1_P: J10.46 J11.3
DSI_LCD_BL_CTRL: J10.66 J11.19
DSI_LCD_INT: J10.62 J11.17
DSI_RESET: J10.68 J11.20 R40.1
DSI_TE: J10.64 J11.18
DVP_D0: J14.45 J22.2
DVP_D1: J14.47 J22.3
DVP_D2: J14.49 J22.4
DVP_D3: J14.51 J22.5
DVP_D4: J14.53 J22.6
DVP_D5: J14.55 J22.7
DVP_D6: J14.57 J22.8
DVP_D7: J14.59 J22.9
DVP_HSYNC: J14.61 J22.10
DVP_PCLK: J14.65 J22.12
DVP_PWDN: J14.69 J22.19
DVP_RST: J7.46 J22.20
DVP_VSYNC: J14.63 J22.11
ETH1_LDO_O: Q6.1 U5.43
ETH1_RESETN: C65.1 D10.1 R108.2 U5.42 U8.4(Y)
ETH_CLK125: C73.1 J14.11 R95.1
ETH_GTX_CLK: J14.17 R48.1
ETH_MDC: J14.31 R73.1 R74.2
ETH_MDINT: J14.39 R89.2 U5.38
ETH_MDIO: J14.33 R84.1 R85.2
ETH_NRST: J14.37 R129.1
ETH_RX_CLK: C28.1 J14.13 R61.1
ETH_RX_DV: J14.9 R53.1
ETH_RXD0: J14.1 R59.1
ETH_RXD1: J14.3 R58.1
ETH_RXD2: J14.5 R57.1
ETH_RXD3: J14.7 R56.1
ETH_TX_EN: J14.27 R41.1
ETH_TXD0: J14.19 R46.1
ETH_TXD1: J14.21 R45.1
ETH_TXD2: J14.23 R44.1
ETH_TXD3: J14.25 R43.1
EXT_12V: D4.1 J17.1 R135.1 R158.1
GATE: D16.2(C) Q7.1 Q8.1 R158.2 R159.1
GBE1_LED_ACT: J13.13(YEL-) R106.1 U5.17
GBE1_LED_LINK: J13.12 R107.1 U5.15
GBE1_TRN0: J13.2 U5.3
GBE1_TRN1: J13.4 U5.6
GBE1_TRN2: J13.8 U5.8
GBE1_TRN3: J13.10 U5.11
GBE1_TRP0: J13.1 U5.2
GBE1_TRP1: J13.3 U5.5
GBE1_TRP2: J13.7 U5.7
GBE1_TRP3: J13.9 U5.10
GPIO_PD10: D2.1 J5.1 J14.24
GPIO_PE6: C94.1 J14.44 R164.2 SW3.2 SW3.4(B2)
GPIO_PF3: J7.54 J19.26
GPIO_PH15: J14.38 R13.1
GPIO_PI0: J14.36 R14.1
GPIO_PI1: J14.34 R134.1
GPIO_PI4: D3.1 J5.2 J14.22
HOST_USB1_DM: J8.A2 L4.2 R72.2 U1.6
HOST_USB1_DP: J8.A3 L4.3 R80.2 U1.1
HOST_USB1_VBUS: C2.1 C3.1 R88.1 U12.7
HOST_USB2_DM: J8.B2 L5.1 R86.1 U7.6
HOST_USB2_DP: J8.B3 L5.4 R87.1 U7.1
HOST_USB2_VBUS: C6.1 C7.1 R90.2 U12.6
HP_L: CON1.5 FB1.2 R176.1 U14.6(I/O4)
HP_R: CON1.3 FB2.2 U14.1
I2C1_SCL: J7.31 J11.11 J19.28 R18.2 U11.17
I2C1_SDA: J7.33 J11.12 J19.27 R21.2 U11.18
I2C2_SCL: J10.31 J22.17 R172.2
I2C2_SDA: J10.33 J22.18 R173.2
I2C4_SCL: D17.1 J1.1 J14.18 J19.5 R55.2
I2C4_SDA: D18.1 J1.2 J14.50 J19.3 R54.2
I2S2_CK: J14.2 J19.12
I2S2_SDI: J14.32 J19.38
I2S2_SDO: J14.6 J19.40
I2S2_WS: J14.4 J19.35
ISET: R105.1 U5.48
LED_MODE: C80.1 R94.1 R95.2 U5.41
LPO_32K: J10.49 R38.2 R39.2
MDC: R73.2 U5.36
MDIO: R84.2 U5.37
MOC1: J14.67 J22.13
MOC2: J7.44 J19.7
NRST: C1.1 D1.1 J7.49 Q1.1 R2.2 R128.1 SW1.2 SW1.4(B2) TP12.1(TP)
OTG_CC1: J2.A5 R122.1 U2.3
OTG_CC2: J2.B5 R121.1 U2.4
OTG_FS_DM: J10.3 L6.4 R120.1
OTG_FS_DP: J10.1 L6.1 R118.1
OTG_FS_ID: J14.12 R123.2 R124.1 TP14.1(TP)
OTG_USB_DM: J2.A7 J2.B7 L6.3 R120.2 U2.6
OTG_USB_DP: J2.A6 J2.B6 L6.2 R118.2 U2.1
OTG_VBUS: J10.7 R125.1
PONKEYN: C102.1 J7.45 SW2.2 SW2.4(B2)
QSPI_BK2_IO0: J10.19 J19.18
QSPI_BK2_IO1: J10.21 J19.22
QSPI_BK2_IO2: J10.23 J19.37
QSPI_BK2_IO3: J10.25 J19.13
QSPI_BK2_NCS: J14.52 J19.16
QSPI_CLK: J14.66 J19.15
R/LINPUT1: C68.1 CON1.1 FB11.1 R116.2 U14.3
RGMII1_RCLK: R61.2 R70.1 U5.35
RGMII1_RCTL: R53.2 R60.1 R66.1 U5.33
RGMII1_RD0: R59.2 R69.1 U5.32
RGMII1_RD1: R58.2 R68.1 U5.31
RGMII1_RD2: R57.2 R64.1 U5.28
RGMII1_RD3: R56.2 R65.1 U5.27
RGMII1_TCLK: C20.1 R48.2 U5.24
RGMII1_TCTL: R41.2 U5.25
RGMII1_TD0: R46.2 U5.19
RGMII1_TD1: R45.2 U5.20
RGMII1_TD2: R44.2 U5.21
RGMII1_TD3: R43.2 U5.22
SAI2_FSAM: J10.16 R145.1
SAI2_MCLKA: J10.20 R137.1
SAI2_SCKAM: J10.14 R140.1
SAI2_SDAM: J10.18 R148.1
SAI2_SDBM: J10.22 R157.1
SD_CD: D12.1 J21.10 R143.2 R146.2
SD_CLK: C14.1 D5.1 J21.5 R37.2 R81.2
SD_CMD: D13.1 J21.3 R153.2 R154.2
SD_DAT0: D6.1 J21.7 R82.2 R83.2
SD_DAT1: D7.1 J21.8 R92.2 R93.2
SD_DAT2: D15.1 J21.1 R141.2 R142.2
SD_DAT3: D14.1 J21.2 R155.2 R156.2
SDMMC1_CD: J10.40 R143.1
SDMMC1_CK: C11.1 J10.38 R37.1
SDMMC1_CMD: J10.36 R154.1
SDMMC1_D0: J10.28 R83.1
SDMMC1_D1: J10.30 R93.1
SDMMC1_D2: J10.32 R142.1
SDMMC1_D3: J10.34 R156.1
SDMMC3_CLK: J10.69 R26.1
SDMMC3_CMD: J10.67 R25.1
SDMMC3_D0: J10.59 R27.1
SDMMC3_D1: J10.61 R28.1
SDMMC3_D2: J10.63 R23.1
SDMMC3_D3: J10.65 R24.1
SPI5_CLK: J10.45 J19.23
SPI5_MISO: J10.43 J19.21
SPI5_MOSI: J10.41 J19.19
SPI5_NSS: J10.17 J19.24
STLINK_SWCLK: J7.53 R111.2
STLINK_SWDIO: J7.51 R101.2
SW: C36.1 L3.1 U9.6
TIM1_CH4: J14.46 J19.31
TIM4_CH3: J7.35 J19.32
TIM4_CH4: J7.37 J19.33
TIM5_CH4: J14.20 J19.29
UART4_RX: J10.27 R97.2 U6.6
UART4_TX: J7.56 R98.2 U6.5
USART1_CTS: J10.55 R79.1
USART1_RTS: J10.57 R76.1
USART1_RX: J10.53 R78.1
USART1_TX: J10.51 R77.1
USART2_CTS: J14.48 J19.36
USART2_RTS: J7.48 J19.11
USART2_RX: J10.2 J19.10
USART2_TX: J10.4 J19.8(TXD0/GPIO14)
USB1_EN: J14.42 R20.2 U12.3
USB1_N: J7.62 L4.1 R72.1
USB1_OC: J14.40 R10.1 U12.8
USB1_P: J7.64 L4.4 R80.1
USB2_EN: J7.52 R17.2 U12.4
USB2_N: J7.68 L5.2 R86.2
USB2_OC: J7.50 R9.1 U12.5(O\C\2\)
USB2_P: J7.70 L5.3 R87.2
VETH1_AVDDH: C52.1 C57.1 C59.1 FB10.2 Q6.3(SOURCE) R103.1 U5.1 U5.12 U5.47
VETH1_AVDDL: C55.1 C58.1 R109.2 U5.4 U5.9
VETH1_AVDDL_PLL: C41.1 C42.1 C43.1 FB9.2 U5.44
VETH1_AVDDL_PMOS: C31.1 FB6.1 FB9.1 Q6.2 Q6.4 R109.1
VETH1_DVDDH: C30.1 C34.1 C62.1 D10.2(C) R62.2 R64.2 R65.2 R66.2 R68.2 R69.2 R70.2 R74.1 R85.1 R89.1 R94.2 R102.1 R104.1 R106.2 R107.2 R108.1 U5.16 U5.34 U5.40 U8.5
VETH1_DVDDL: C32.1 C33.1 FB6.2 U5.14 U5.18 U5.23 U5.26 U5.30 U5.39
WL_HOST_WAKE: J14.28 R19.2 U3.13
WL_REG_ON: J14.30 R133.1
N303234: J13.11 R104.2
N303238: J13.14 R102.2
N303440: C51.2 R100.2 U5.46 X3.1
N303536: C47.2 R100.1 U5.45(XO) X3.3
N303624: C48.1 J13.5 J13.6 R103.2
N303732: R128.2 R129.2 U8.2
N3772447: TP6.1(TP) U3.28
N3772513: TP5.1(TP) U3.27
N3772517: TP9.1(TP) U3.26
N3772521: TP8.1(TP) U3.25
N3772562: TP7.1(TP) U3.4
N3774700: C9.1 R30.2 X1.1
N3775644: R49.2 R51.2 U3.2
N3776012: R22.2 R133.2 U3.12
N3776054: R23.2 R31.1 U3.14
N3776279: R24.2 R32.1 U3.15
N3776286: R25.2 R33.1 U3.16
N3776293: R26.2 R34.1 U3.17
N3776300: R27.2 R35.1 U3.18
N3776307: R28.2 R36.1 U3.19
N3776951: R38.1 U3.24
N3777387: R42.1 U3.29
N3779189: C22.1 R51.1 R52.2
N3779193: C21.1 J16.1 R52.1
N3780208: ANT1.1 C23.1 R50.1
N3780222: C24.1 R49.1 R50.2
N3787372: J7.55 TP2.1(TP)
N3787386: J7.57 TP15.1(TP)
N3787400: J7.59 TP1.1(TP)
N3793884: L1.1 U3.21
N3794135: C49.1 L1.2 U3.23
N3820313: C26.1 C27.1 C29.1 R63.2 R67.2 U4.2(VIN)
N3820535: C44.1 C46.1 C63.1 L2.2 R75.1 R99.1 U4.5
N3820638: R71.1 R75.2 U4.7
N3835690: J8.A4 R110.1
N3835694: J8.B4 R114.1
N3839488: C77.1 R119.2 U12.2
N3854640: C13.1 C15.1 FB3.2 J11.14 J11.15
N3854714: C97.1 C100.1 FB14.2 J22.15 J22.16
N3873950: J2.B1 J2.B12 R132.2
N3874122: J2.B4 J2.B9 R130.1
N3911606: R167.1 SW3.1 SW3.3
N3915722: Q3.3 R3.1 R5.1
N3915999: Q2.3 R7.1 R8.1
N3917680: J9.2 R15.2
N3931666: CON1.4 R176.2
N3973979: J9.5(COM2) R16.1
N3987111: LED1.1 R1.2
N3987115: Q1.3 R1.1
N3990987: R67.1 R160.2 R161.1 U4.8
N3991147: C19.1 TP4.1(TP) U4.1
N3991771: L2.1 U4.3
N4046258: C74.2 R126.1 U11.4
N4046262: C78.1 C79.1 R131.2 U11.32
N4046268: C72.1 C76.1 R117.2 U11.8 U11.10
N4046299: C93.1 C95.1 R165.2 U11.21 U11.26
N4056572: R145.2 R152.1 U11.13
N4056576: R140.2 U11.12
N4056580: R157.2 U11.16
N4056584: R148.2 U11.14
N4056588: R137.2 U11.11
N4058145: R152.2 U11.15
N4058376: C90.1 C92.1 U11.27(VMID)
N4058385: C70.1 C75.1 R116.1 U11.1
N4059055: TP16.1(TP) U11.30
N4059075: C81.1 U11.31
N4059079: C84.1 U11.29
N4059170: C4.1 C81.2 FB1.1 R4.1
N4059174: C5.1 C84.2 FB2.1 R6.1
N4060621: C71.1 C74.1 FB11.2
N4439955: D9.1 J24.1 R91.1 R96.1 U6.2
N4439995: D8.1 J24.2 U6.3
N4458088: D20.1 R101.1 R112.2 TP10.1(TP)
N4458139: D21.1 R111.1 R113.2 TP11.1(TP)
N4473305: J8.A1 R88.2 U1.5(VCC)
N4473534: J8.B1(VBUS_B) R90.1 U7.5(VCC)
N4505708: R126.2 U11.5
N4522056: Q9.3 R11.2 R12.1
N4540513: R115.1 U9.4
N4540517: C36.2 R115.2
N4540641: R127.2 U9.3
N4540827: C40.1 C45.1 C50.1 C53.1 L3.2 R136.1 R139.1
N4540887: C54.1 R138.1 U9.2(VCC)
N4540895: R138.2 U9.8
N4541105: R144.1 U9.1
N4541109: R139.2 R144.2 R147.1
N4563547: Q7.2(S) R150.2 R151.1
N4563559: Q7.3 Q8.3
N4588094: LED2.1 R13.2
N4589189: LED3.1 R14.2
N4589271: LED5.1 R134.2
N4607134: LED4.1 R162.2

Pads without a net: J2 A8 B8 S2 S4; J7 11 13 15 17 18 19 20 21 22 23 24 26 28 29 30 32 34 38 39 40 41 43 63 65 67 69; J8 S1 S2; J10 5 11 13 15 24 35 37 39; J11 21 22 23 24 25 26 27 28 29 30 31 32 33 34 35 36 37 38 39 40; J14 8 10 16 26 41 54 62 64 68 70; J17 3; J21 11 12 15 16; U1 3 4; U3 5 8 30 32 35 37 38 39 40 45 46 47; U7 3 4; U8 1; U11 2 3 6 7 19 22 23 25

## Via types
v1: diameter 0.406, hole 0.203, TOP to BOTTOM, 874 vias

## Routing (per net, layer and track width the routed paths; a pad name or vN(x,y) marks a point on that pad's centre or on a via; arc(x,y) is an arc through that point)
3V3_DC: length 59
  TOP w0.305: R162.1 v1(8.54,18.39)
  TOP w0.381: R40.2 38.77,76.29 39.15,76.67 v1(39.15,76.68) ; v1(18.19,23.34) 19.09,22.45 21.11,22.45 22.13,23.47 22.13,28.8 22.89,29.56 24,29.56 24.29,29.27 v1(24.29,28.79) ; R18.1 21.95,74.35 v1(22.18,74.11) 22.42,74.35 R21.1
  TOP w0.406: J5.3 v1(7.53,46.31)
  TOP w0.508: J1.3 9.23,61.42 v1(9.53,61.72)
  LYR3 w0.381: v1(27.32,76.3) 28.23,77.21 28.23,80.74 27.59,81.38 15.61,81.38 v1(15,81.99)
  LYR4 w0.381: v1(39.15,76.68) 39.15,76.2 38.88,75.93 38.88,73.82 39.1,73.6 v1(39.1,73.12) ; v1(18.19,23.34) 15.65,23.34 14.38,22.07 12.23,22.07 v1(8.54,18.39)
  BOTTOM w0.381: v1(9.53,61.72) R173.1 9.54,61.09 R172.1 ; FB13.1 v1(15,81.99) ; v1(40.9,66.7) 41.06,66.86 41.6,66.86 41.87,66.59 R131.1 ; v1(20.99,52.27) 21.36,52.27 R62.1 21.42,52.21 v1(20.99,51.79) ; v1(12.35,56.11) 12.05,56.41 FB14.1
  BOTTOM w0.406: R117.1 v1(45.99,57.26)
  vias: v1(12.35,55.6) v1(21.37,63.47) v1(21.5,65.25) v1(22,65.25) v1(24.04,64.11) v1(24.04,63.6) v1(24.04,63.09) v1(24.29,28.29) v1(24.54,64.11) v1(24.54,63.6) v1(24.54,63.09) v1(26.87,76.15) v1(38.51,72.35) v1(39.02,72.62) v1(39.02,72.11) v1(44.36,73.38) v1(44.36,72.87)
3V3_RPI: length 2
  BOTTOM w0.381: 46.04,71.16 R55.1 46.04,72.13 R54.1 45.19,72.13 v1(45.09,72.23)
  vias: v1(44.18,74.68) v1(44.38,74.22) v1(45.09,71.73)
3V3_SD: length 52.8
  TOP w0.381: v1(14.97,78.94) 15.58,78.33 v1(17.51,78.33)
  LYR4 w0.381: v1(17.51,78.33) 18.4,77.44 18.4,75.87 17.43,74.9 v1(17.43,73.78) ; 38.01,81.6 37.63,81.98 ; 38.01,81.6 38.39,81.98 ; 38.01,81.6 38.01,80.18 v1(39,79.19) ; 38.01,81.6 38.01,81.98 ; 37.63,81.98 38.01,81.98 ; 37.63,81.98 v1(16.8,81.98) 16.8,80.77 v1(14.97,78.94) ; 38.01,81.98 38.39,81.98 ; 38.39,81.98 39.63,81.98 v1(40.55,82.9)
  BOTTOM w0.381: R92.1 v1(39,79.19) ; FB12.2 FB13.2 ; FB13.2 16.79,81.99 v1(16.8,81.98) C83.1 18.04,81.98 C82.1 19.17,82.54 19.4,82.31 J21.4 ; FB13.2 16.24,81.89 15.48,81.12 R153.1 ; v1(17.51,78.33) 17.9,77.94 R141.1 ; v1(40.55,82.9) 40.52,82.87 R81.1 R82.1 ; R155.1 v1(14.97,78.94) ; R146.1 17.71,72.51 17.43,72.79 v1(17.43,73.78)
3V3_SYS: length 40.4
  TOP w0.203: 44.48,39.98 44.46,40 J7.5 ; J7.1 44.3,39.2 45.42,38.07 v1(47.53,38.07) v1(48.04,38.07) ; J7.7 44.44,40.4 44.48,40.36 ; J7.9 44.3,40.8 44.48,40.61 ; 44.61,39.6 44.61,39.6 J7.3
  TOP w0.254: U6.8 43.43,19.89 ; 43.43,19.89 43.37,19.95 43.37,20.41 43.55,20.59 43.8,20.59 43.98,20.41 U6.7 ; 43.43,19.89 42.86,19.89 v1(42.67,19.7) ; R91.2 42.87,18.6 43.48,17.99 U6.1
  TOP w0.305: R2.1 3.09,13.05 Q1.2 v1(3.69,13.79)
  TOP w0.381: R91.2 42.12,19.66 C35.2 v1(42.67,19.7) ; v1(47.92,20.43) R98.1 47.91,19.83 R97.1 ; Q3.2 17.25,65.51 17.39,65.36 J9.4 18.03,67.32 16.61,68.74 v1(15.98,68.74) Q2.2 ; R164.1 v1(18.53,74.56)
  TOP w0.508: J9.1 23.11,72.02 22.75,72.38 22.02,72.38 v1(21.62,71.98)
  BOTTOM w0.381: R112.1 v1(13.02,80.01) R113.1 ; R9.2 13.24,19.4 v1(13.5,19.15) ; v1(15.98,68.74) 15.47,68.74 15.02,69.18 Q9.2 ; v1(37.88,47.09) 36.86,48.1 R160.1 ; FB12.1 v1(14.97,83.01) ; R10.2 v1(16.8,28.85) ; R123.1 v1(15.76,54.68)
  vias: v1(17.94,63.73) v1(18.32,63.47) v1(18.68,63.11) v1(18.83,65.25) v1(36.1,72.74) v1(36.1,72.23) v1(47.53,37.56) v1(47.53,37.06) v1(48.04,37.56) v1(48.04,37.06)
3V3_WIFI: length 16.6
  TOP w0.381: R47.2 43.11,59.51 v1(42.71,59.92) ; v1(28.63,66.78) 28.74,66.78 28.74,66.78 R36.2 ; v1(28.74,67.77) 28.76,67.75 R35.2 ; v1(35.53,61.19) 35.3,60.96 R39.1 ; R33.2 v1(28.7,69.7) ; R31.2 28.7,71.63 28.62,71.72 v1(28.61,71.72) ; R19.1 v1(19.86,75.65) ; R32.2 v1(28.61,70.67) ; R34.2 v1(28.72,68.71)
  LYR4 w0.381: v1(19.86,75.65) 19.86,74 21.37,72.48 27.84,72.48 v1(28.61,71.72)
  vias: v1(30.01,62.33) v1(30.01,61.74) v1(34.58,75.77) v1(35.09,75.79)
5V_IN: length 33.5
  TOP w0.203: 47.59,41.6 v1(47.99,41.2) J7.12 ; 47.59,41.6 47.59,41.61 47.21,42 J7.16 ; 47.59,41.6 J7.14 ; J7.6 v1(47.64,40) ; J7.2 v1(47.64,39.2) ; J7.8 v1(48,40.4) ; J7.10 v1(47.6,40.8) ; J7.4 v1(47.91,39.6)
  LYR4 w0.508: v1(32.04,61.44) 33.56,61.44 34.58,60.42 40.93,60.42 42.45,58.9 47.91,58.9 ; 47.91,58.9 47.91,59.03 v1(48.42,59.53) v1(48.42,59.03) 48.29,58.9 47.91,58.9
  BOTTOM w0.381: R165.1 v1(32.04,61.44) ; R63.1 v1(33.56,45.73)
  vias: v1(26.83,27.66) v1(26.83,27.15) v1(33.56,46.71) v1(33.56,46.2) v1(34.07,46.71) v1(34.07,46.2) v1(34.07,45.69)
5V_RPI: length 6.8
  BOTTOM w0.502: J19.4 53.78,75.09 ; J19.4 54.76,74.11 ; J19.4 52.8,74.11 ; J19.4 53.78,73.14 ; 53.78,75.68 J19.2 ; J19.2 54.76,76.65 ; J19.2 52.8,76.65
5V_USB: length 8.6
  TOP w0.381: v1(12.78,29.18) 14.89,29.18 v1(15.65,29.94) v1(16.16,30.45)
  BOTTOM w0.381: 11.97,29.18 v1(12.78,29.18) ; v1(16.16,30.45) 16.14,30.48 15.96,30.48 15.68,30.76 15.68,30.93 v1(15.65,30.96) 15.4,31.22 15.07,31.22 14.14,32.14 R130.2 ; R150.1 v1(35.11,33.65)
  vias: v1(15.65,30.45) v1(16.16,30.96) v1(16.16,29.94) v1(34.58,33.63) v1(34.58,33.12) v1(35.09,33.12) v1(35.59,33.63) v1(35.59,33.12)
GND: length 647.6
  TOP w0.203: J10.9 36.44,51.2 v1(36.74,50.9) ; J10.54 31.19,42.4 31.19,42.4 v1(30.79,42.4) ; v1(36.57,47.06) 36.43,47.2 J10.29 ; v1(33.18,38.83) 32.82,39.2 J10.70 ; J7.36 47.46,46 v1(47.53,46.07) ; J7.66 v1(47.28,52) ; v1(19.86,60.33) 19.95,60.24 J14.35 ; v1(19.86,60.33) 20.25,60.33 20.34,60.42 21.18,60.42 21.55,60.05 J14.43 ; v1(19.86,60.33) 18.99,60.33 18.75,60.09 J14.29 ; v1(15.17,57.52) 15.55,57.14 J14.14 ; J7.42 v1(47.51,47.2) ; v1(17.18,58.01) 16.42,58.01 15.95,58.47 J14.15 ; J10.48 v1(30.71,43.6) ; J10.26 31.46,48 31.29,47.82 v1(31.29,47.23) ; v1(45.12,66.75) 44.04,65.67 ; J10.42 v1(33.39,44.8) ; J7.60 47,50.8 47.4,50.4 v1(47.4,50.4) J7.58 ; J10.47 v1(36.68,43.6) ; v1(41.94,51.66) 42.41,51.2 J7.61 ; v1(44.36,48.61) 44.15,48.4 J7.47 ; J10.60 v1(33.39,41.2) ; J10.12 30.81,50.8 30.2,51.41 v1(29.81,51.41)
  TOP w0.254: 23.4,73.25 23.36,73.29 22.93,73.29 ; 23.4,73.25 23.4,72.72 23.72,72.41 23.72,72.07 23.91,71.87 24.75,71.87 24.84,71.79 25.96,71.79 26.86,72.69 X1.2 ; 23.4,73.25 23.4,74.14 23.81,74.54 X1.4 24.69,74.92 25.14,75.37 27.93,75.37 C8.2 28.5,74.85 29.19,75.54 C13.2 ; U6.4 v1(44.98,17.61) ; v1(38.53,58.73) 39.25,59.45 R42.2
  TOP w0.305: J16.3 v1(48.52,66.39) ; J16.2 44.79,64.97 44.08,65.67 44.04,65.67 ; C24.2 48.19,76.45 v1(48.22,76.48) 48.19,76.5 C23.2 48.19,77.44 v1(48.22,77.47) ; C11.2 30.41,46.34 v1(30.67,46.09) ; C22.2 47.83,70.09 47.84,70.09 v1(47.84,69.64) 47.84,69.2 47.81,69.18 C21.2 47.81,67.58 v1(47.84,67.56)
  TOP w0.381: R114.2 v1(22.51,19.78) ; R114.2 22.51,21.65 ; R114.2 23.27,20.8 v1(23.53,20.55) ; R114.2 21.85,20.8 ; 29.6,76.3 C13.2 28.78,76.3 ; C18.2 37.68,77.26 ; C18.2 37.14,76.75 ; C18.2 v1(37.14,77.92) ; C18.2 v1(36.57,77.26) ; J17.2 48.09,3.98 ; J17.2 43.79,3.98 ; J17.2 45.94,2.83 ; J17.2 45.94,5.14 ; v1(19.34,77.31) 18.5,78.15 J11.1 ; v1(41.99,82.67) 42.07,82.6 ANT1.3 ; J9.3 18.03,71.79 v1(18.73,72.49) ; J9.3 18.5,71.71 ; J9.3 17.56,71.71 ; C7.2 15.02,22.19 ; C7.2 15.02,19.6 ; C7.2 14.3,20.9 ; C7.2 15.25,20.9 v1(15.91,21.56) ; 53.78,70.6 J19.6 ; J19.6 53.78,72.55 ; J19.6 52.8,71.57 ; J11.16 v1(33.5,80.55) ; J11.16 33.5,78.52 ; J11.16 33.1,79.42 ; J12.1 30.17,60.37 ; J12.1 28.32,58.52 ; J12.1 32.02,58.52 ; v1(21.75,80.62) 21.5,80.37 J11.4 v1(21.5,78.08) ; v1(23.11,66.77) J9.6 ; J9.6 23.11,64.58 ; J9.6 22.64,65.36 ; J9.6 23.58,65.36 ; LED4.2 1.98,18.36 ; LED4.2 v1(1.45,19.16) ; LED4.2 1.45,17.7 ; J11.13 v1(30.5,80.5) ; U3.1 v1(41.9,74.86) ; U3.1 41.9,73.31 ; U3.1 42.3,74.06 ; SW2.1 8.25,82.5 ; SW2.1 7.69,83.37 ; SW2.1 SW2.3 ; 39.81,59.1 R42.2 40.22,59.45 ; C17.2 36.41,77.26 ; C17.2 35.87,76.75 ; C17.2 35.87,77.76 ; C17.2 35.34,77.26 ; 1.23,2.84 SW1.3 ; SW1.3 v1(1.79,4.19) SW1.1 ; SW1.3 2.35,2.84 ; v1(22.18,73.55) 22.66,73.55 22.93,73.29 ; 15.1,74.54 R167.2 ; R167.2 16.06,74.54 v1(16.07,74.55) C94.2 ; R167.2 15.45,74.49 C102.2 ; R167.2 15.5,74.2 ; J6.1 46.85,26.38 ; J6.1 48.7,24.53 ; J6.1 46.85,22.67 ; 41.31,19.29 C35.1 ; C35.1 41.31,20.1 ; C35.1 38.93,19.7 v1(38.13,18.89) ; 28.44,75.2 C8.2 28.04,74.85 ; C2.2 v1(7.32,19.58) ; C2.2 8.05,21.03 ; C2.2 v1(6.49,21.03) ; C2.2 7.32,22.33 ; 45.26,16.89 U6.4 44.98,16.38 ; 53.85,4.34 J24.3 52.87,3.36 ; ANT1.2 49.13,82.6 v1(49.26,82.47) ; J19.9 51.24,67.47 ; J19.9 50.26,66.49 ; J19.9 51.24,65.52 ; 50.26,46.17 J19.25 ; J19.25 51.24,45.2 ; J19.25 51.24,47.15 ; SW1.1 1.79,7.31 ; SW1.1 2.35,6.44 ; v1(27.34,45.82) 27.61,45.55 C14.2 ; J5.4 v1(7.53,48.31) ; J5.4 10.8,48.31 ; J5.4 9.25,47.65 ; C22.2 47.83,71.6 arc(47.83,71.63) v1(47.81,71.65) ; U3.36 v1(43.92,65.67) ; C10.2 28.13,61.91 28.1,61.95 v1(28.1,62.1) ; C10.2 27.63,61.44 ; C10.2 28.13,60.91 ; C10.2 28.63,61.44 ; v1(21.24,75.92) 21.21,75.89 21.21,75.6 20.81,75.2 R22.1 ; v1(24.5,78.12) J11.7 v1(24.5,80.53) ; C15.2 33.24,77.74 ; C15.2 34.16,76.96 ; C15.2 33.24,76.17 ; C15.2 32.45,76.96 ; 33.02,19.61 LED3.2 32.36,20.15 ; v1(40.08,74.96) 40.08,74.73 40.1,74.71 U3.3 ; C1.2 v1(3.18,11.63) ; C1.2 2.68,12.04 ; C1.2 2.68,11.22 ; v1(42.71,16.48) 43.11,16.08 D9.2 ; 34.32,77.04 C16.2 ; C16.2 35.14,77.04 ; C16.2 34.73,77.21 v1(35.09,77.57) ; 48.54,76.02 C24.2 48.19,75.61 ; 52.8,41.09 J19.30 53.78,40.12 ; D8.2 45.83,15.4 ; D8.2 45.48,15 ; D8.2 45.48,17.28 45.15,17.61 v1(44.98,17.61) ; v1(51.41,17.32) J20.2 v1(49.98,16.26) ; J19.39 52.22,28.39 ; J19.39 51.24,29.37 ; J19.39 50.26,28.39 ; J19.39 51.24,27.42 ; 52.8,53.79 J19.20 ; J19.20 53.78,52.82 ; J19.20 53.78,54.77 ; SW2.3 8.25,78.9 ; SW2.3 v1(7.69,77.78) ; SW2.3 7.13,78.9 ; LED1.2 1.52,9.75 ; LED1.2 v1(1.52,8.26) ; LED1.2 2.05,9.09 ; J15.1 12.78,26.38 ; J15.1 10.93,24.53 ; J15.1 12.78,22.67 ; J15.1 14.64,24.53 ; U7.2 21.75,17.5 v1(22.51,18.26) ; 45.57,66.24 J16.2 45.57,63.7 ; v1(16.42,19.78) 16.92,20.29 R110.2 ; R11.1 15.4,73.78 ; R11.1 15.4,72.97 ; R11.1 v1(16.04,73.38) ; C20.2 11.99,62.3 11.44,62.86 J1.4 7.51,62.86 7.02,63.36 v1(7.02,63.85) ; v1(34.96,65.76) 34.48,65.76 34.39,65.67 U3.20 ; CON1.2 11.4,76.55 ; CON1.2 11.4,74.74 ; CON1.2 10,75.65 ; J19.14 53.78,62.39 ; J19.14 53.78,60.44 ; J19.14 52.8,61.41 ; 49.18,64.97 J16.3 48.52,63.7 ; X1.2 27.16,72.53 C9.2 ; 52.8,36.01 J19.34 ; J19.34 53.78,35.04 ; J19.34 53.78,36.99 ; 25.5,74.54 X1.4 24.69,73.86 ; 16.58,74.21 C94.2 ; C94.2 16.99,74.55 ; R110.2 17.59,20.8 ; R110.2 16.26,20.8 ; R110.2 16.92,21.65 ; 2.68,10.33 D1.2 ; D1.2 2.68,11.15 ; D1.2 v1(3.31,10.74) ; 28.61,62.18 C12.2 ; C12.2 27.72,62.58 ; C12.2 28.61,62.99 ; J11.1 18.1,79.42 ; J11.1 18.5,80.33 ; U1.2 15.52,17.51 15.25,17.78 15.25,18.61 v1(15.78,19.15) ; R96.2 40.1,17.56 39.4,18.26 v1(38.13,18.26) ; 28.61,19.61 LED5.2 ; LED5.2 29.27,20.15 ; LED5.2 29.27,19.08 ; R7.2 12.4,65.56 R5.2 12.83,65.54 12.86,65.5 v1(12.94,65.5) ; U3.31 40.1,63.66 40.37,63.93 41.49,63.93 41.9,63.52 U3.33 41.9,62.34 42.38,61.86 v1(42.79,61.86) ; J11.10 v1(27.5,80.52)
  TOP w0.406: LED5.2 LED2.2 LED3.2
  TOP w0.508: ANT1.2 48.3,80.99 48.8,80.49 ; 42.45,80.36 42.85,80.76 ANT1.3
  LYR2_GND w0.381: 28.32,58.52 J12.1 ; J12.1 30.17,60.37 ; J12.1 30.17,56.66 ; J12.1 32.02,58.52 ; CON1.2 11.4,76.55 ; CON1.2 10,75.65 ; CON1.2 12.81,75.65 ; CON1.2 11.4,74.74 ; 53.78,60.44 J19.14 ; J19.14 53.78,62.39 ; J19.14 52.8,61.41 ; 50.26,46.17 J19.25 ; J19.25 51.24,47.15 ; J19.25 51.24,45.2 ; J19.25 52.22,46.17 ; 53.78,40.12 J19.30 52.8,41.09 ; 53.78,52.82 J19.20 ; J19.20 52.8,53.79 ; J19.20 53.78,54.77 ; J15.1 12.78,26.38 ; J15.1 12.78,22.67 ; J15.1 10.93,24.53 ; J15.1 14.64,24.53 ; 45.94,2.83 J17.2 ; J17.2 43.79,3.98 ; J17.2 45.94,5.14 ; J17.2 48.09,3.98 ; J19.39 52.22,28.39 ; J19.39 50.26,28.39 ; J19.39 51.24,29.37 ; J19.39 51.24,27.42 ; 53.85,4.34 J24.3 52.87,3.36 ; 46.85,22.67 J6.1 ; J6.1 48.7,24.53 ; J6.1 46.85,26.38 ; J6.1 45,24.53 ; J19.6 53.78,72.55 ; J19.6 52.8,71.57 ; J19.6 53.78,70.6 ; 53.78,35.04 J19.34 ; J19.34 53.78,36.99 ; J19.34 52.8,36.01 ; 50.26,66.49 J19.9 ; J19.9 51.24,67.47 ; J19.9 52.22,66.49 ; J19.9 51.24,65.52
  LYR5_PWR w0.381: 51.24,65.52 J19.9 ; J19.9 51.24,67.47 ; J19.9 52.22,66.49 ; J19.9 50.26,66.49 ; 52.8,61.41 J19.14 ; J19.14 53.78,60.44 ; J19.14 53.78,62.39 ; J19.6 53.78,72.55 ; J19.6 53.78,70.6 ; J19.6 52.8,71.57
  BOTTOM w0.203: C60.2 40.78,40.37 40.29,40.87 v1(40.04,40.87) ; U4.6 v1(34.18,50.76) ; C61.2 41.06,38.62 40.64,38.2 40.64,38.04 v1(40.55,37.94) ; v1(30.64,65.35) 30.72,65.43 31.02,65.43 31.04,65.45 C5.2 R6.2 32.62,65.45 32.89,65.71 32.89,65.78 34.17,67.06 35.13,67.06 35.98,66.21 v1(35.98,65.25)
  BOTTOM w0.254: 38.1,59.16 v1(38.53,58.73) ; 38.1,59.16 36.78,60.48 U11.24 ; 38.1,59.16 38.1,59.96 38.28,60.15 U11.28 ; v1(38.53,58.73) 40.28,56.97 U11.9 ; v1(38.53,58.73) 38.28,58.48 U11.20
  BOTTOM w0.305: C57.2 25.77,32.98 25.53,32.73 v1(25.47,32.73) ; C77.2 27.61,26.53 27.82,26.74 v1(28.38,26.74) ; C71.2 15.98,66.59 v1(16.16,66.77) ; v1(25.81,22.45) 25.81,22.54 25.43,22.92 R20.1 ; U8.3 21.2,32.7 21.5,32.99 v1(22.13,32.99) ; X3.4 25.65,38.71 26.46,39.52 26.46,41.74 26.45,41.75 ; C4.2 R4.2 32.56,68.51 31.77,69.29 J21.9 32.72,70.22 32.86,70.08 v1(33.31,70.08) ; C68.2 13,65.44 v1(12.94,65.5) ; C80.2 21.34,45.53 21.15,45.35 v1(20.97,45.35) ; U5.13 v1(11.6,41.49) ; v1(24.54,21.18) 25,21.64 R17.1 ; C59.2 v1(24.7,29.92) ; U5.29 15.46,46.52 v1(16.16,45.82)
  BOTTOM w0.381: v1(26.32,44.92) 25.84,44.92 25.57,44.66 C73.2 ; 43.79,3.98 J17.2 ; J17.2 45.94,2.83 ; J17.2 48.09,3.98 ; J17.2 v1(45.94,6) ; D12.2 v1(18.73,72.49) ; D12.2 18.32,71.76 ; D12.2 19.13,71.76 ; C42.2 v1(22.33,42.06) 22.56,41.83 C47.1 23.36,41.32 X3.2 ; C42.2 22.86,42.42 C43.2 ; C42.2 21.93,42.95 ; C42.2 22.74,42.95 ; C42.2 22.28,43 21.5,43 C41.2 21.45,42.82 v1(21.75,42.52) ; 25,22.31 R17.1 25.35,21.91 ; 25.05,32.46 C62.2 ; C62.2 25.05,33.27 ; C62.2 25.4,32.86 ; 21.42,49.55 C34.2 ; C34.2 21.42,50.37 ; C34.2 20.66,49.96 20.33,49.63 v1(19.85,49.63) ; v1(8.3,19.26) 10.43,19.26 10.7,19.53 C3.2 ; 13.44,4.83 R149.2 ; R149.2 v1(14.41,5.91) ; R149.2 15.38,4.83 ; C26.2 26.58,51.29 ; C26.2 25,51.29 ; C26.2 25.79,50.72 ; C26.2 25.79,51.85 ; v1(36.57,47.06) 36.13,47.06 C19.2 ; 10,75.65 CON1.2 ; CON1.2 12.81,75.65 ; CON1.2 11.4,74.74 ; CON1.2 11.4,76.55 ; 24.96,38.58 X3.4 ; X3.4 26.33,38.58 ; X3.4 v1(25.65,37.6) ; 20.9,32.02 U8.3 21.2,31.51 ; D16.1 37.26,34.79 ; D16.1 36.41,33.94 ; D16.1 38.11,33.94 ; D16.1 v1(37.26,32.88) ; 38.22,24.28 C39.2 ; C39.2 37.69,24.78 ; C39.2 38.22,25.28 ; C39.2 38.76,24.78 ; v1(9.81,54.86) 10.4,55.45 C97.2 ; U12.1 21.7,26.65 ; U12.1 20.98,26.23 20.35,26.86 v1(20.35,27.15) ; U12.1 22.84,26.23 ; U12.1 21.7,25.82 ; C57.2 26.62,32.98 ; C57.2 26.12,33.51 ; C57.2 26.12,32.44 ; v1(15.53,38.54) 15.53,38.45 15.64,38.34 C55.2 ; 12.76,41.19 U5.13 13.27,41.49 ; C65.2 v1(18.99,32.33) ; C65.2 20.17,32.33 ; C65.2 19.64,32.83 ; C65.2 19.64,31.83 ; C28.2 20.3,51.52 ; C28.2 19.9,51.18 ; C28.2 19.49,51.52 ; 46.85,22.67 J6.1 ; J6.1 45,24.53 ; J6.1 46.85,26.38 ; J6.1 48.7,24.53 ; 14.02,65.44 C68.2 13.61,65.1 ; v1(43.72,53.44) 44.11,53.82 C72.2 ; 11.72,48.84 C33.2 ; C33.2 11.37,49.25 ; C33.2 11.72,49.65 ; 10.91,50.38 C32.2 ; C32.2 11.41,49.84 ; C32.2 11.91,50.38 ; C32.2 11.41,50.91 ; v1(14.29,53.18) 14.29,53.34 14.49,53.55 R124.2 ; C52.2 20.1,38.52 ; C52.2 19.29,38.52 ; C52.2 v1(19.7,38.05) ; C75.2 43.31,61.38 ; C75.2 42.5,61.38 ; C75.2 42.91,61.72 ; U14.5 10.57,64.77 ; U14.5 10.57,62.96 ; U14.5 11,64.11 ; 10.57,62.96 11.21,62.96 11.52,63.28 U14.4 ; 10.57,62.96 10.57,62.68 11.68,61.57 11.68,61.54 v1(11.71,61.54) ; 40.56,38.65 C61.2 ; C61.2 41.06,39.19 ; C61.2 41.56,38.65 ; 36.1,46.68 C19.2 ; C19.2 36.1,47.49 ; C19.2 36.45,47.09 ; v1(33.43,42.52) 34.52,43.6 C56.2 ; C46.2 24.23,53.71 ; C46.2 24.23,52.71 ; C46.2 24.76,53.21 ; C95.2 34.09,61.55 C93.2 v1(34.45,61.44) ; C95.2 33.24,62.05 ; C95.2 32.71,61.55 ; 52.87,3.36 J24.3 53.85,4.34 ; C72.2 44.64,55.45 ; C72.2 43.32,55.45 C76.2 ; C72.2 44.11,55.95 ; 28.32,58.52 J12.1 ; J12.1 30.17,60.37 ; J12.1 32.02,58.52 ; J12.1 30.17,56.66 ; 50.26,46.17 J19.25 ; J19.25 51.24,45.2 ; J19.25 51.24,47.15 ; 34.9,65.07 C92.2 ; C92.2 35.48,64.99 C90.2 ; C92.2 35.4,65.61 ; C92.2 35.8,65.07 35.97,65.25 v1(35.98,65.25) ; C92.2 35.4,64.54 ; C76.2 43.3,55.88 ; C76.2 42.83,55.88 42.2,55.24 v1(42.2,53.43) ; C76.2 42.9,55.53 ; C38.2 41.03,26.04 ; C38.2 40.06,26.9 ; C38.2 39.1,26.04 ; C38.2 40.06,25.19 ; 42.3,25.19 C37.2 ; C37.2 42.3,26.9 ; C37.2 43.26,26.04 ; C37.2 41.33,26.04 ; C53.2 46.22,28.43 ; C53.2 45.15,28.43 ; C53.2 45.69,28.93 ; C53.2 45.69,27.93 ; 29.21,22.36 C54.2 ; C54.2 29.72,22.9 ; C54.2 29.18,22.9 v1(28.61,23.47) ; C54.2 29.21,23.43 ; 27.61,23.74 C77.2 26.88,25.04 ; 25.8,52.56 C63.2 ; C63.2 26.59,53.12 ; C63.2 25.01,53.12 ; C63.2 25.8,53.69 ; C45.2 43.07,28.19 ; C45.2 42.29,28.75 ; C45.2 42.29,27.62 ; C45.2 41.5,28.19 ; R105.2 v1(21.55,39.77) ; 24.96,23.33 R20.1 24.96,22.52 ; 48.58,15.75 C25.2 ; C25.2 48.58,16.76 ; C25.2 48.05,16.26 ; C25.2 49.12,16.26 ; D11.1 45.23,21.33 ; D11.1 45.23,18.74 ; D11.1 44.06,20.03 ; D11.1 46.39,20.03 ; U4.4 31.49,51.41 ; U4.4 29.96,51.41 ; U4.4 30.72,51.77 ; J19.39 52.22,28.39 ; J19.39 50.26,28.39 ; J19.39 51.24,27.42 ; J19.39 51.24,29.37 ; C60.2 41.35,40.27 ; C60.2 40.78,39.48 ; C60.2 40.22,40.27 ; C78.2 43.11,64.87 v1(43.92,65.67) ; C78.2 42.25,64.34 ; C78.2 42.25,65.4 ; C78.2 41.75,64.87 ; C83.2 18,83.19 ; C83.2 17.47,82.69 ; C83.2 16.95,83.19 16.92,83.16 v1(16.79,83.16) ; C83.2 17.59,83.3 C82.2 ; D5.2 v1(38.57,82.85) ; 9.61,55.72 C97.2 ; C97.2 10.4,56.51 ; C97.2 11.18,55.72 ; 3.98,64.41 J22.22 ; J22.22 2.58,65.57 ; J22.22 v1(3.98,67.15) ; J22.22 5.38,65.57 ; C40.2 40.01,29.21 ; C40.2 40.01,27.5 ; C40.2 40.98,28.36 ; C40.2 39.05,28.36 ; v1(39.06,80.24) 39.02,80.24 39,80.21 D7.2 ; v1(8.9,51) 9.08,51.18 D17.2 ; R122.2 11.9,34.03 ; R122.2 v1(11.56,34.59) ; R122.2 11.56,33.63 ; v1(9.56,50.64) 9.59,50.61 D2.2 ; C58.2 16.01,36.83 v1(16.54,36.29) ; C58.2 16.51,36.89 ; C58.2 15.51,36.89 ; C6.2 11.59,20.57 ; C6.2 11.24,20.16 ; C6.2 11.59,18.36 11.34,18.11 v1(11.34,17.62) ; 31.2,68.03 C4.2 31.6,68.38 ; 43.34,28.15 C50.2 ; C50.2 44.13,28.71 ; C50.2 44.92,28.15 ; C50.2 44.13,27.59 ; D3.2 9.45,50.66 ; D3.2 8.63,50.66 ; D3.2 9.04,51 ; 34.7,39.71 R151.2 ; R151.2 35.11,40.06 ; R151.2 35.52,39.71 ; v1(17.81,32.86) 18.08,32.59 C98.2 ; v1(34.01,58.13) 33.99,58.15 C49.2 ; D20.2 v1(14.32,81.57) ; D18.2 v1(9.65,51.48) ; 26.45,41.75 26.34,41.86 24.11,41.86 23.8,42.18 ; D14.2 v1(17.9,80.53) D13.2 ; v1(33.31,21.43) 33.26,21.38 R147.2 ; J22.14 v1(4.92,57.07) ; J22.14 6.13,56.69 ; J22.14 6.13,57.44 ; C44.2 27.93,53.65 ; C44.2 26.96,52.79 ; C44.2 28.89,52.79 ; 23.8,42.18 X3.2 ; 23.8,42.18 C43.2 ; X3.2 24.48,40.88 ; X3.2 23.11,40.88 ; 47.02,15.97 R135.2 ; R135.2 47.43,16.31 ; R135.2 47.84,15.97 ; 53.78,35.04 J19.34 53.78,36.99 ; 2.58,41.57 J22.21 ; J22.21 5.38,41.57 ; J22.21 3.98,42.72 ; J22.21 v1(3.98,39.6) ; U14.2 v1(10.57,67.41) ; R124.2 14.49,54.07 ; R124.2 14.15,53.67 ; C91.2 v1(12.12,5.97) ; C91.2 11.16,4.83 ; C91.2 13.09,4.83 ; D2.2 10,50.96 ; D2.2 10.41,50.61 ; 53.78,62.39 J19.14 53.78,60.44 ; C100.2 9.28,57.12 ; C100.2 8.87,56.77 ; C100.2 8.47,57.12 ; C27.2 27.36,51.37 ; C27.2 27.9,50.87 ; C27.2 26.83,50.87 ; C27.2 27.36,50.37 ; v1(16.21,44.24) 18.92,44.24 ; v1(16.21,44.24) 13.51,44.24 ; v1(16.21,44.24) 16.21,41.54 ; v1(16.21,44.24) 16.21,46.95 ; C48.2 v1(31.76,8.83) ; C48.2 31.17,8.49 ; C48.2 30.77,8.83 ; C51.1 22.56,37.99 v1(22.39,37.82) ; R121.2 v1(10.08,28.78) ; C43.2 23.55,42.92 ; C43.2 23.55,41.92 ; C43.2 24.09,42.42 ; 44.18,61.66 C70.2 ; C70.2 44.18,62.33 v1(43.49,63.01) 42.78,63.73 C79.2 ; C70.2 43.64,62.16 ; 6.13,44.06 v1(4.82,44.06) ; 6.13,44.06 6.13,44.44 ; 6.13,44.06 6.13,43.69 ; 6.13,44.06 7.28,44.06 ; 30.91,43.37 C31.2 ; C31.2 32.61,43.37 ; C31.2 31.76,44.33 ; C56.2 35.03,41.86 ; C56.2 35.03,45.34 ; 34.28,24.23 U9.5 ; U9.5 35.13,24.53 ; U9.5 35.98,24.23 ; C3.2 10.7,20.57 ; C3.2 11.05,20.16 ; D15.2 v1(17.05,78.94) ; 11.1,64.11 U14.4 ; U14.4 11.95,64.11 ; U14.4 11.52,64.77 ; C73.2 24.6,44.32 ; C73.2 24.19,44.66 ; 18.08,31.19 C98.2 ; C98.2 17.52,31.98 ; C98.2 18.65,31.98 ; C90.2 35.48,63.46 ; C90.2 35.83,63.86 ; 36.12,48.69 R161.2 ; R161.2 36.12,49.5 ; R161.2 36.71,49.09 36.84,49.22 v1(36.86,49.22) ; C79.2 41.83,64.13 ; C79.2 41.83,63.32 ; 52.8,71.57 J19.6 53.78,70.6 ; v1(36.48,81.38) 36.25,81.61 J21.6 ; v1(11.6,41.49) 11.49,41.39 7.41,41.39 v1(6.64,40.61) ; D6.2 v1(39,81.23) ; D21.2 v1(10.45,80.97) ; C30.2 21.59,51.08 ; C30.2 21.09,50.55 ; C30.2 20.59,51.08 ; C99.2 17.52,30.89 ; C99.2 17.52,30.07 ; C99.2 v1(17.91,30.48) ; TP13.1 7.75,82.04 v1(8.54,81.25) ; 25.55,31 C59.2 23.85,31 ; v1(36.74,50.9) 36.3,50.9 R71.2 ; R60.2 v1(17.86,52.8) ; U2.2 v1(16.29,29.18) ; 53.78,52.82 J19.20 53.78,54.77
  BOTTOM w0.406: v1(29.04,53.31) 28.44,53.31 C44.2 27.93,51.4 v1(28.04,51.28)
  vias: v1(9.56,55.6) v1(11.59,6.7) v1(12.73,6.7) v1(13.24,5.94) v1(13.24,4.67) v1(13.88,6.7) v1(14.38,45.82) v1(14.38,44.29) v1(14.38,42.52) v1(14.89,6.7) v1(15.4,5.94) v1(16.04,6.7) v1(16.16,42.52) v1(17.81,45.82) v1(17.94,44.29) v1(17.94,42.52) v1(19.85,50.14) v1(24.42,71.73) v1(26.07,75.41) v1(26.7,53.31) v1(26.7,51.15) v1(27.97,50.77) v1(28.48,75.28) v1(29.24,75.92) v1(37.12,59.79) v1(37.5,84.4) v1(38.13,25.37) v1(38.29,83.64) v1(38.51,59.79) v1(38.64,58.01) v1(38.9,26.51) v1(38.9,24.74) v1(39.12,84.38) v1(39.53,40.74) v1(40.04,83.66) v1(40.6,84.4) v1(40.52,76.07) v1(40.93,36.67) v1(41.05,73) v1(41.18,28.29) v1(41.18,27.15) v1(41.18,25.63) v1(41.38,83.66) v1(41.38,76.86) v1(41.54,81.84) v1(41.56,79.52) v1(41.59,78.13) v1(41.96,84.4) v1(42.02,80.9) v1(42.1,77.44) v1(42.58,76.91) v1(42.65,75.54) v1(42.71,74.09) v1(42.78,79.5) v1(42.81,78.15) v1(43.09,27.05) v1(43.37,77.44) v1(43.34,74.8) v1(43.34,5.94) v1(43.34,4.54) v1(43.34,3.15) v1(44.1,75.56) v1(44.13,76.91) v1(44.74,5.94) v1(44.99,77.44) v1(44.99,2.77) v1(45.09,68.4) v1(45.14,27.76) v1(45.7,76.86) v1(45.98,72.74) v1(46.03,66.77) v1(46.11,75.43) v1(46.16,69.64) v1(46.11,68.47) v1(47.02,27.02) v1(47.02,21.94) v1(47.02,6.07) v1(47.15,63.5) v1(47.28,2.77) v1(47.46,74.04) v1(47.61,75.43) v1(47.96,66.8) v1(48.04,5.94) v1(48.29,63.47) v1(48.29,3.91) v1(48.34,79.98) v1(48.34,78.56) v1(48.42,27.02) v1(48.42,21.82) v1(48.42,17.37) v1(49.36,84.32) v1(49.41,80.06) v1(49.46,78.66) v1(49.46,77.52) v1(50.71,84.43) v1(50.73,78.3)
